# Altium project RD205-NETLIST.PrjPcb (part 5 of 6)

## Sheet 8.SchDoc
size 398 x 287 mm
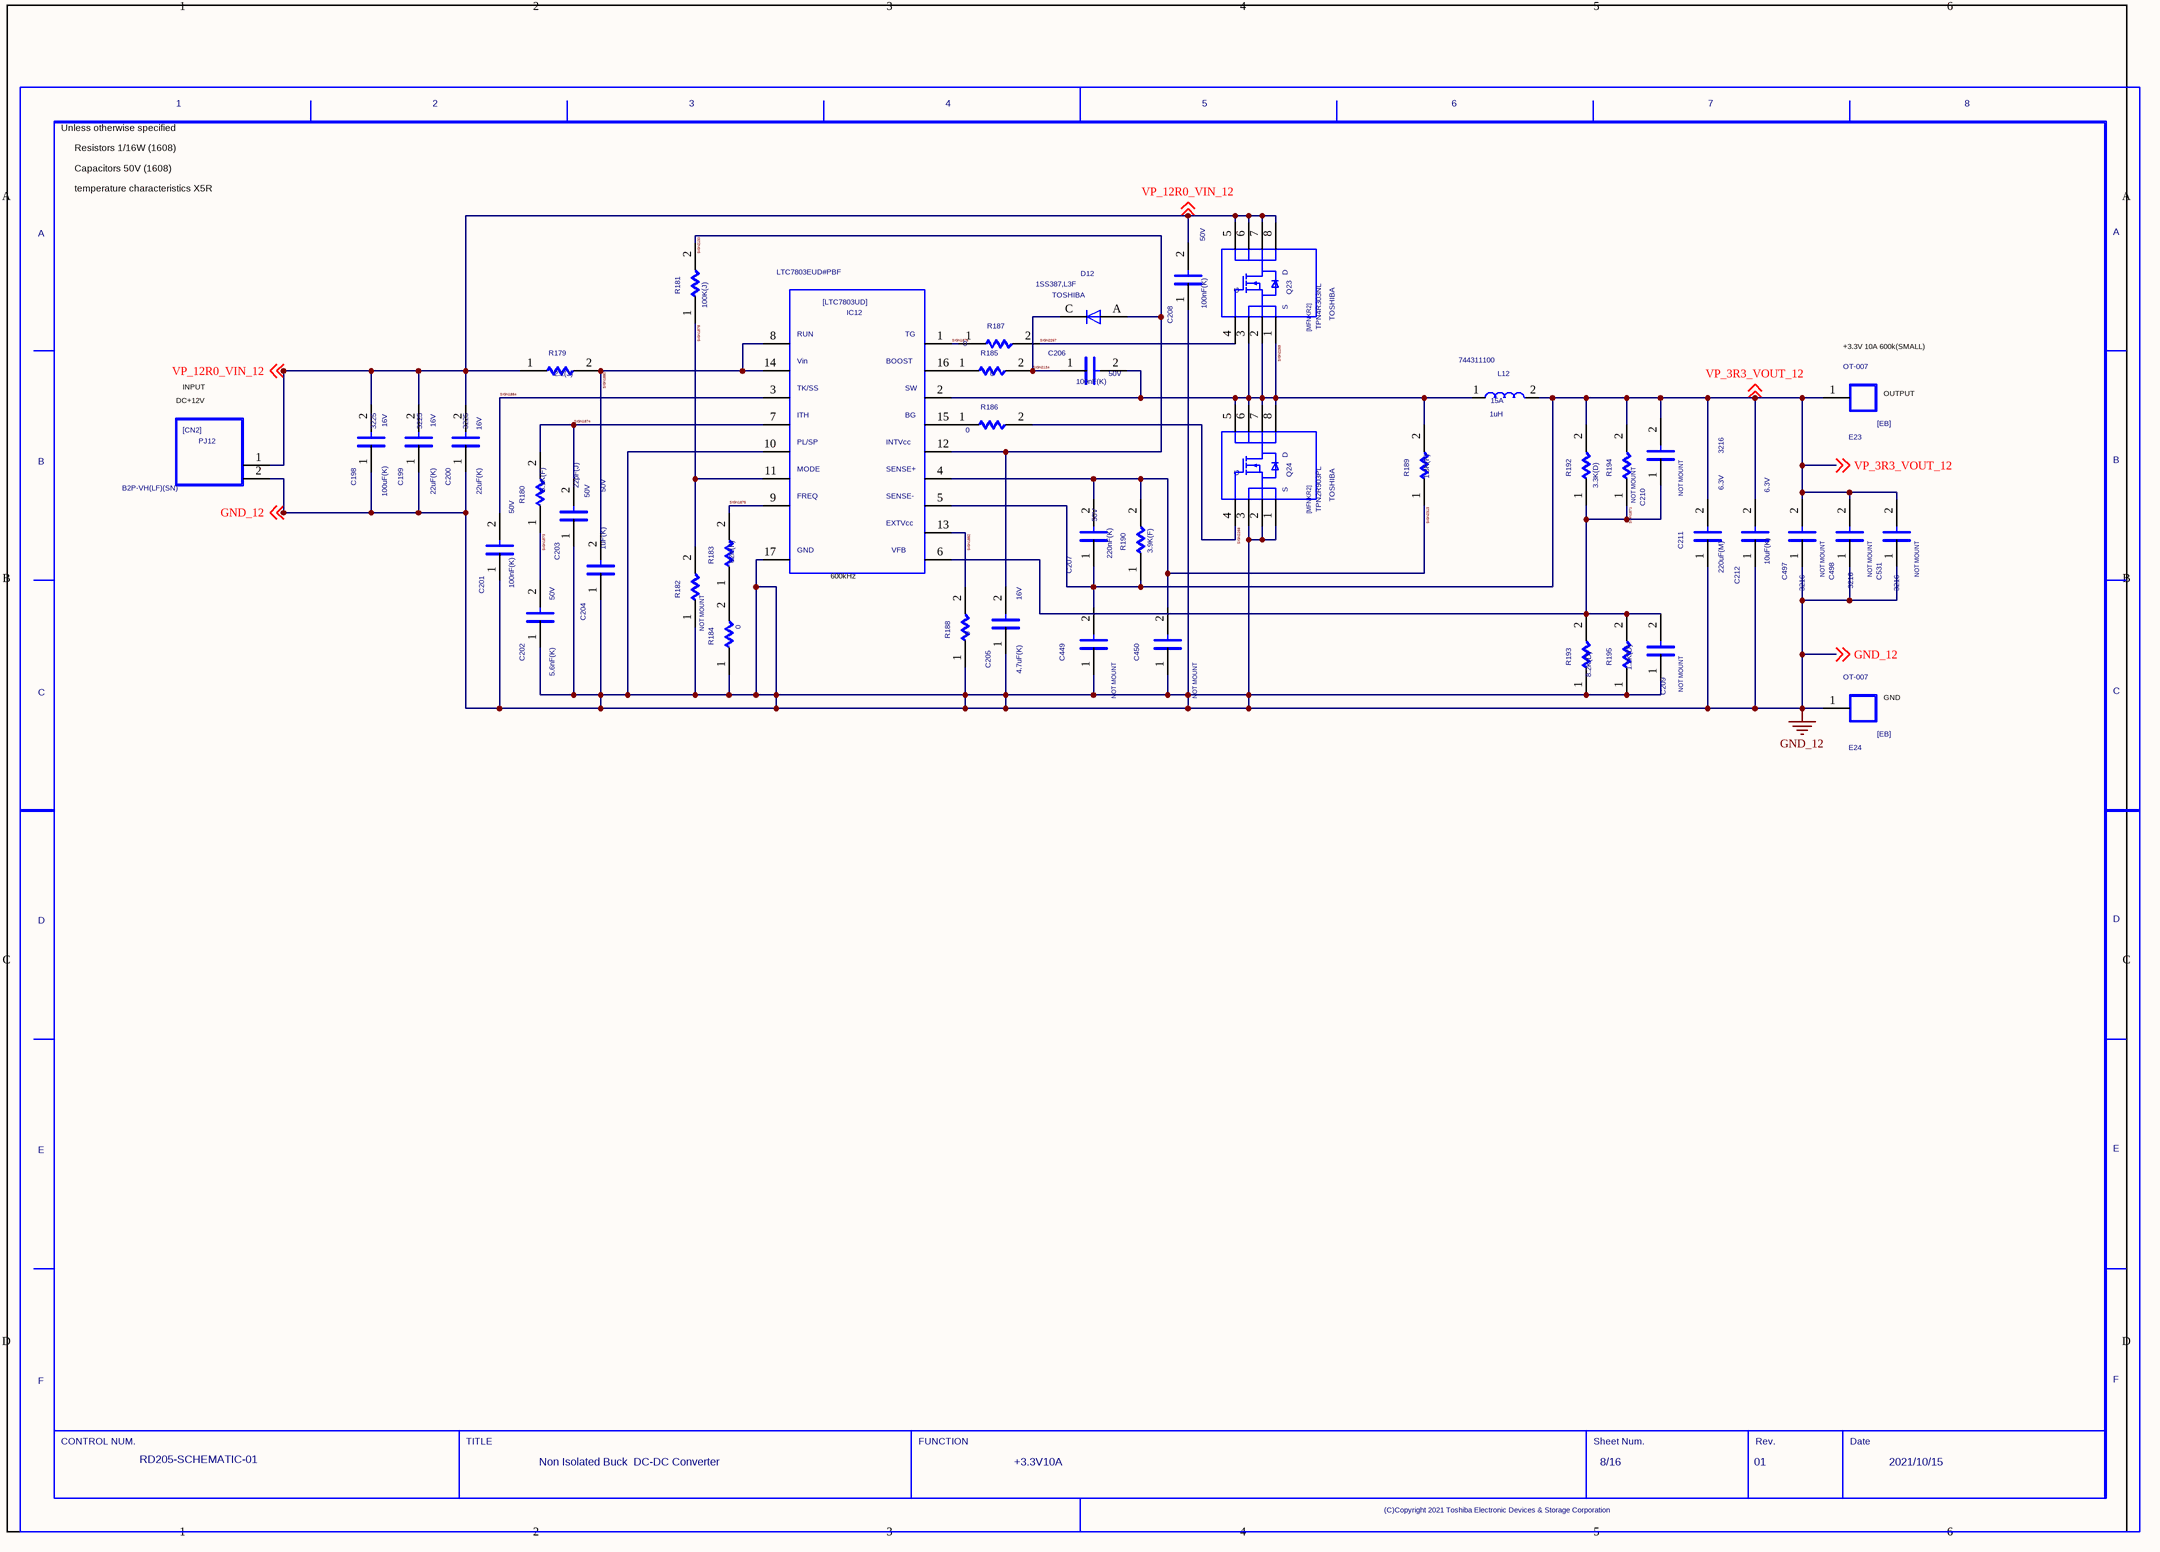
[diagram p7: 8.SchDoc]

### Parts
(Parts that share a designator on the sheet are numbered #1, #2 ... from top to bottom, then left to right.)
C198  SIZECODESMD: 3225  VAL2: 16V  VAL1: 100uF(K)  (hidden comment: C)
C199  SIZECODESMD: 3225  VAL2: 16V  VAL1: 22uF(K)  (hidden comment: C)
C200  SIZECODESMD: 3225  VAL2: 16V  VAL1: 22uF(K)  (hidden comment: C)
C201  VAL2: 50V  VAL1: 100nF(K)  (hidden comment: C)
C202  VAL2: 50V  VAL1: 5.6nF(K)  (hidden comment: C)
C203  VAL2: 50V  VAL1: 22pF(J)  (hidden comment: C)
C204  VAL2: 50V  VAL1: 1uF(K)  (hidden comment: C)
C205  VAL2: 16V  VAL1: 4.7uF(K)  (hidden comment: C)
C206  VAL2: 50V  VAL1: 100nF(K)  (hidden comment: C)
C207  VAL2: 50V  VAL1: 220nF(K)  (hidden comment: C)
C208  VAL2: 50V  VAL1: 100nF(K)  (hidden comment: C)
C209  NOTMOUNT: NOT MOUNT  (hidden comment: C)
C210  NOTMOUNT: NOT MOUNT  (hidden comment: C)
C211  SIZECODESMD: 3216  VAL2: 6.3V  VAL1: 220uF(M)  (hidden comment: C)
C212  VAL2: 6.3V  VAL1: 10uF(K)  (hidden comment: C)
C449  NOTMOUNT: NOT MOUNT  (hidden comment: C)
C450  NOTMOUNT: NOT MOUNT  (hidden comment: C)
C497  NOTMOUNT: NOT MOUNT  SIZECODESMD: 3216  (hidden comment: C)
C498  NOTMOUNT: NOT MOUNT  SIZECODESMD: 3216  (hidden comment: C)
C531  NOTMOUNT: NOT MOUNT  SIZECODESMD: 3216  (hidden comment: C)
D12  USERCOMPTEXT3: TOSHIBA  VAL3: 1SS387,L3F  (hidden comment: D)
E23  VAL3: OT-007  (hidden comment: EB)
E24  VAL3: OT-007  (hidden comment: EB)
IC12  VAL3: LTC7803EUD#PBF  (hidden comment: LTC7803UD)
L12  VAL3: 744311100  VAL2: 15A  VAL1: 1uH  (hidden comment: L)
PJ12  VAL3: B2P-VH(LF)(SN)  (hidden comment: CN2)
Q23  USERCOMPTEXT3: TOSHIBA  VAL3: TPN4R303NL  (hidden comment: MFNKR2)
Q24  USERCOMPTEXT3: TOSHIBA  VAL3: TPN2R903PL  (hidden comment: MFNKR2)
R179  VAL1: 2.2(J)  (hidden comment: R)
R180  VAL1: 5.1K(F)  (hidden comment: R)
R181  VAL1: 100K(J)  (hidden comment: R)
R182  NOTMOUNT: NOT MOUNT  (hidden comment: R)
R183  VAL1: 62K(F)  (hidden comment: R)
R184  VAL1: 0  (hidden comment: R)
R185  VAL1: 0  (hidden comment: R)
R186  VAL1: 0  (hidden comment: R)
R187  VAL1: 0  (hidden comment: R)
R188  VAL1: 0  (hidden comment: R)
R189  VAL1: 1.3K(F)  (hidden comment: R)
R190  VAL1: 3.9K(F)  (hidden comment: R)
R192  VAL1: 3.3K(D)  (hidden comment: R)
R193  VAL1: 8.2K(D)  (hidden comment: R)
R194  NOTMOUNT: NOT MOUNT  (hidden comment: R)
R195  VAL1: 1.2K(D)  (hidden comment: R)
U?#8  DATE: 2021/10/15  SHEETNUMBER: 8/16  TITLE: Non Isolated Buck / DC-DC Converter  REVISION: 01  DRAWINGNUMBER: RD205-SCHEMATIC-01  FUNCTION: +3.3V10A  (hidden comment: WAKU_DEF100)

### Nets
GND_12: C198.1 C199.1 C200.1 C201.1 C202.1 C203.1 C204.1 C205.1 C208.1 C209.1 C211.1 C212.1 C449.1 C450.1 C497.1 C498.1 C531.1 E24.1 IC12.10 IC12.17 PJ12.2 Q24.1 Q24.2 Q24.3 R182.1 R184.1 R188.1 R193.1 R195.1 ; off-sheet GND_12
SIGN1871: C209.2 C210.1 IC12.6 R192.1 R193.2 R194.1 R195.2
SIGN1873: C202.2 R180.1
SIGN1874: C203.2 IC12.7 R180.2
SIGN1875: IC12.9 R183.2
SIGN1876: IC12.1 R187.1
SIGN1878: IC12.11 R181.1 R182.2
SIGN1880: C204.2 IC12.8 IC12.14 R179.2
SIGN1882: IC12.13 R188.2
SIGN1884: C201.2 IC12.3
SIGN2133: C205.2 D12.A IC12.12 R181.2
SIGN2134: C206.1 D12.C R185.2
SIGN2267: Q23.4 R187.2
SIGN2268: Q24.4 R186.2
SIGN2269: C206.2 IC12.2 L12.1 Q23.1 Q23.2 Q23.3 Q24.5 Q24.6 Q24.7 Q24.8 R189.2
SIGN2313: C207.2 C450.2 IC12.4 R189.1 R190.2
VP_3R3_VOUT_12: C207.1 C210.2 C211.2 C212.2 C449.2 C497.2 C498.2 C531.2 E23.1 IC12.5 L12.2 R190.1 R192.2 R194.2 ; off-sheet VP_3R3_VOUT_12
VP_12R0_VIN_12: C198.2 C199.2 C200.2 C208.2 PJ12.1 Q23.5 Q23.6 Q23.7 Q23.8 R179.1 ; off-sheet VP_12R0_VIN_12
NetIC12_15: IC12.15 R186.1
NetIC12_16: IC12.16 R185.1
NetR183_1: R183.1 R184.2

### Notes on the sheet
- Unless otherwise specified
- Capacitors 50V (1608)
- Resistors 1/16W (1608)
- temperature characteristics X5R
- DC+12V
- INPUT
- (near E23) +3.3V 10A 600k(SMALL)
- (near E23) OUTPUT
- (near IC12) 600kHz
- (near E24) GND

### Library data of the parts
C198 = C: SQ_PART_MODEL: CON_100n; FNPARTSNAMEG: CHIP CERAMIC CAPACITOR (3225); USEINPARTSLIST: YES; OriginalSymbolOrigin: (2540,7620); MFSOLDERINGPROP: .; TEMPCHARACTERI2: B; MFFORMINGDIVP: KC; OUMECLASSIFICATION: セラミックコンデンサ; MFMOUNTSYMBOLP: 90; CDMASTERCADCELG: DC903A; PCODE: P03276001115; FNCLASSCODEG: P03-03; MAXGCOUNT: 1; RATEDVOLTAGE: 250; COMPONENTNAME: G36030160049; OUMEMAKER: KYC 京セラ; MFPACKAGEMETHOP: S; NOMINALCAPACITA: 100n; OUMEMAKERKATAMEI: CF32W5R104K250AT; CAPACITANCETOLE: K
C199 C200 = C: SQ_PART_MODEL: CON_22u; FNPARTSNAMEG: CHIP CERAMIC CAPACITOR (3225); USEINPARTSLIST: YES; OriginalSymbolOrigin: (2540,7620); MFSOLDERINGPROP: .; TEMPCHARACTERI2: B; MFFORMINGDIVP: KC; OUMECLASSIFICATION: セラミックコンデンサ; MFMOUNTSYMBOLP: 80; CDMASTERCADCELG: DC903A; PCODE: P03043035626; FNCLASSCODEG: P03-03; MAXGCOUNT: 1; RATEDVOLTAGE: 6.3; COMPONENTNAME: G36030119054; OUMEMAKER: TYD 太陽誘電; MFPACKAGEMETHOP: S; NOMINALCAPACITA: 22u; OUMEMAKERKATAMEI: JMK325BJ226KM-T; CAPACITANCETOLE: K
C201 C206 C208 = C: SQ_PART_MODEL: CON_100n; FNPARTSNAMEG: CHIP CERAMIC CAPACITOR (1608); USEINPARTSLIST: YES; OriginalSymbolOrigin: (2540,7620); MFSOLDERINGPROP: .; TEMPCHARACTERI2: B; MFFORMINGDIVP: KC; OUMECLASSIFICATION: セラミックコンデンサ; SIZECODESMD: 1608; MFMOUNTSYMBOLP: 80; CDMASTERCADCELG: C8100E; PCODE: P03B000000E4; FNCLASSCODEG: P03-03; MAXGCOUNT: 1; RATEDVOLTAGE: 16; COMPONENTNAME: GDM030000598; OUMEMAKER: MRT 村田製作所; MFPACKAGEMETHOP: S; NOMINALCAPACITA: 100n; OUMEMAKERKATAMEI: GRM188B11C104KA01C; CAPACITANCETOLE: K
C202 = C: SQ_PART_MODEL: CON_5.6n; FNPARTSNAMEG: CHIP CERAMIC CAPACITOR (1608); USEINPARTSLIST: YES; OriginalSymbolOrigin: (2540,7620); TOLERANCE: K; ASIMVALUE: 5.6N; MFSOLDERINGPROP: .; TEMPCHARACTERI2: B; MFFORMINGDIVP: KC; OUMECLASSIFICATION: セラミックコンデンサ; SIZECODESMD: 1608; MFMOUNTSYMBOLP: 80; CDMASTERCADCELG: C8100E; PCODE: P03039100222; FNCLASSCODEG: P03-03; MAXGCOUNT: 1; RATEDVOLTAGE: 50; COMPONENTNAME: G36030011068; OUMEMAKER: MRT 村田製作所; MFPACKAGEMETHOP: S; OUMEMAKERKATAMEI: GRM39B562K50PT
C203 = C: SQ_PART_MODEL: CON_22p; FNPARTSNAMEG: CHIP CERAMIC CAPACITOR (1608); USEINPARTSLIST: YES; OriginalSymbolOrigin: (2540,7620); TOLERANCE: J; ASIMVALUE: 22P; CDMASTERCADCELG: C8100E; MFSOLDERINGPROP: .; TEMPCHARACTERI2: CH; MFFORMINGDIVP: KC; OUMECLASSIFICATION: セラミックコンデンサ; SIZECODESMD: 1608; MFMOUNTSYMBOLP: 80; PCODE: P03039A02625; FNCLASSCODEG: P03-03; MAXGCOUNT: 1; RATEDVOLTAGE: 50; COMPONENTNAME: G36030011129; OUMEMAKER: TYD 太陽誘電; MFPACKAGEMETHOP: S; OUMEMAKERKATAMEI: UMK107CH220JZ-T
C204 = C: SQ_PART_MODEL: CON_1u; FNPARTSNAMEG: CHIP CERAMIC CAPACITOR (1608); USEINPARTSLIST: YES; OriginalSymbolOrigin: (2540,7620); MFSOLDERINGPROP: .; TEMPCHARACTERI2: B; MFFORMINGDIVP: KC; OUMECLASSIFICATION: セラミックコンデンサ; SIZECODESMD: 1608; MFMOUNTSYMBOLP: 80; CDMASTERCADCELG: C8100E; PCODE: P03039ACE122; FNCLASSCODEG: P03-03; MAXGCOUNT: 1; RATEDVOLTAGE: 6.3; COMPONENTNAME: G36030104159; OUMEMAKER: KYC 京セラ; MFPACKAGEMETHOP: S; NOMINALCAPACITA: 1u; OUMEMAKERKATAMEI: CM105B105K06ATN; CAPACITANCETOLE: K
C205 = C: SQ_PART_MODEL: CON_4.7u; FNPARTSNAMEG: CHIP CERAMIC CAPACITOR (1608); USEINPARTSLIST: YES; OriginalSymbolOrigin: (2540,7620); MFSOLDERINGPROP: .; TEMPCHARACTERI2: B; MFFORMINGDIVP: KC; OUMECLASSIFICATION: セラミックコンデンサ; SIZECODESMD: 1608; MFMOUNTSYMBOLP: 80; CDMASTERCADCELG: C8100E; PCODE: P03B000000MS; FNCLASSCODEG: P03-03; MAXGCOUNT: 1; RATEDVOLTAGE: 4; COMPONENTNAME: GDM030000053; OUMEMAKER: KYC 京セラ; MFPACKAGEMETHOP: S; NOMINALCAPACITA: 4.7u; OUMEMAKERKATAMEI: CM105B475M04AT; CAPACITANCETOLE: M
C207 = C: SQ_PART_MODEL: CON_220n; FNPARTSNAMEG: CHIP CERAMIC CAPACITOR (1608); PARTCOMMENT: 代表セル<KC0008> がフットプリントに登録されていません。; USEINPARTSLIST: YES; OriginalSymbolOrigin: (2540,7620); MFSOLDERINGPROP: .; TEMPCHARACTERI2: B; MFFORMINGDIVP: KC; OUMECLASSIFICATION: セラミックコンデンサ; SIZECODESMD: 1608; MFMOUNTSYMBOLP: 80; CDMASTERCADCELG: KC0008; PCODE: P03B000001L3; FNCLASSCODEG: P03-03; MAXGCOUNT: 1; RATEDVOLTAGE: 16; COMPONENTNAME: GDM030001129; OUMEMAKER: MRT 村田製作所; MFPACKAGEMETHOP: S; NOMINALCAPACITA: 220n; OUMEMAKERKATAMEI: GRM188B11C224KA01D; CAPACITANCETOLE: K
C209 C210 = C: SQ_PART_MODEL: CON_100p; FNPARTSNAMEG: CHIP CERAMIC CAPACITOR (1608); USEINPARTSLIST: YES; OriginalSymbolOrigin: (2540,7620); TOLERANCE: J; ASIMVALUE: 100P; MFSOLDERINGPROP: .; TEMPCHARACTERI2: CH; MFFORMINGDIVP: KC; OUMECLASSIFICATION: セラミックコンデンサ; SIZECODESMD: 1608; MFMOUNTSYMBOLP: 80; CDMASTERCADCELG: C8100E; PCODE: P03039177125; FNCLASSCODEG: P03-03; MAXGCOUNT: 1; RATEDVOLTAGE: 50; COMPONENTNAME: G36030011365; OUMEMAKER: KYC 京セラ; MFPACKAGEMETHOP: S; OUMEMAKERKATAMEI: CM105CH101J50AT; VAL2: 50V; VAL1: 100pF(J)
C211 = C: SQ_PART_MODEL: CON_22u; FNPARTSNAMEG: CHIP CERAMIC CAPACITOR (3216); USEINPARTSLIST: YES; OriginalSymbolOrigin: (2540,7620); MFSOLDERINGPROP: .; TEMPCHARACTERI2: B; MFFORMINGDIVP: KC; OUMECLASSIFICATION: セラミックコンデンサ; MFMOUNTSYMBOLP: 80; CDMASTERCADCELG: DC901A; PCODE: P03B0000004V; FNCLASSCODEG: P03-03; MAXGCOUNT: 1; RATEDVOLTAGE: 6.3; COMPONENTNAME: GDM030000020; OUMEMAKER: KYC 京セラ; MFPACKAGEMETHOP: S; NOMINALCAPACITA: 22u; OUMEMAKERKATAMEI: CM316B226M06AT; CAPACITANCETOLE: M
C212 = C: SQ_PART_MODEL: CON_1u; FNPARTSNAMEG: CHIP CERAMIC CAPACITOR (1608); PARTCOMMENT: 代表セル<KC0008> がフットプリントに登録されていません。; USEINPARTSLIST: YES; OriginalSymbolOrigin: (2540,7620); MFSOLDERINGPROP: .; TEMPCHARACTERI2: B; MFPACKAGEMETHOP: S; MFFORMINGDIVP: KC; MFMOUNTSYMBOLP: 80; PCODE: P03B000000ZQ; OUMECLASSIFICATION: セラミックコンデンサ; SIZECODESMD: 1608; CDMASTERCADCELG: KC0008; FNCLASSCODEG: P03-03; MAXGCOUNT: 1; RATEDVOLTAGE: 6.3; COMPONENTNAME: GDM030000202; OUMEMAKER: MRT 村田製作所; NOMINALCAPACITA: 1u; OUMEMAKERKATAMEI: GRM185B10J105KE21D; CAPACITANCETOLE: K
C449 C450 = C: SQ_PART_MODEL: CON_220n; FNPARTSNAMEG: CHIP CERAMIC CAPACITOR (1608); PARTCOMMENT: 代表セル<KC0008> がフットプリントに登録されていません。; USEINPARTSLIST: YES; OriginalSymbolOrigin: (2540,7620); MFSOLDERINGPROP: .; TEMPCHARACTERI2: B; MFFORMINGDIVP: KC; OUMECLASSIFICATION: セラミックコンデンサ; SIZECODESMD: 1608; MFMOUNTSYMBOLP: 80; CDMASTERCADCELG: KC0008; PCODE: P03B000001L3; FNCLASSCODEG: P03-03; MAXGCOUNT: 1; RATEDVOLTAGE: 16; COMPONENTNAME: GDM030001129; OUMEMAKER: MRT 村田製作所; MFPACKAGEMETHOP: S; NOMINALCAPACITA: 220n; OUMEMAKERKATAMEI: GRM188B11C224KA01D; VAL2: 16V; VAL1: 220nF(K); CAPACITANCETOLE: K
C497 C498 C531 = C: SQ_PART_MODEL: CON_22u; FNPARTSNAMEG: CHIP CERAMIC CAPACITOR (3216); USEINPARTSLIST: YES; OriginalSymbolOrigin: (2540,7620); MFSOLDERINGPROP: .; TEMPCHARACTERI2: B; MFFORMINGDIVP: KC; OUMECLASSIFICATION: セラミックコンデンサ; MFMOUNTSYMBOLP: 80; CDMASTERCADCELG: DC901A; PCODE: P03B0000004V; FNCLASSCODEG: P03-03; MAXGCOUNT: 1; RATEDVOLTAGE: 6.3; COMPONENTNAME: GDM030000020; OUMEMAKER: KYC 京セラ; MFPACKAGEMETHOP: S; NOMINALCAPACITA: 22u; OUMEMAKERKATAMEI: CM316B226M06AT; VAL2: 6.3V; VAL1: 22uF(M); CAPACITANCETOLE: M
D12 = D: FNPARTSNAMEG: DIODE; USEINPARTSLIST: YES; PARTNAME: GDM420000143; SAVEAREA0: -565,-171,12979,8058; SAVECOUNT: 1; TIME: 14:49:55; UPDATEUSER: 19870035; UPDATETIME: 14:20:16; OriginalSymbolOrigin: (5080,5080); FORWARDVOLTAGEM: 0; MAXREVERSEVOLTA: 80; COMPONENTNAME: GDM420000143_package; MFSOLDERINGPROP: .; OUMEMAKER: TSB 東芝（ＹＰＳＳ）; QUADMODEL: dummymodel; MFPACKAGEMETHOP: S; MFFORMINGDIVP: MM; MOUNTINGFORMSMD: SMD; OUMECLASSIFICATION: 小信号ダイオード; OUMEMAKERKATAMEI: 1SS387(TPH3,F); CDMASTERCADCELG: D8101D; PCODE: P42B0000008E; FNCLASSCODEG: P42-01
E23 E24 = EB: FNPARTSNAMEG: TERMINAL; USEINPARTSLIST: YES; PARTNAME: 5P9L1232P001; OUMEPARTTYPE: TB; OriginalSymbolOrigin: (2540,12700); COMPONENTNAME: 5P9L1232P001_package; MAXGCOUNT: 1; MFSOLDERINGPROP: .; OUMEMAKER: オサダ; QUADMODEL: dummymodel; MFPACKAGEMETHOP: I; MFFORMINGDIVP: OD; OUMECLASSIFICATION: 端子台、端子板; CDMASTERCADCELG: DE0009; KIND: PBS; PCODE: P29045001117; TERMINALSTYLE: SC; FNCLASSCODEG: P29-01
IC12 = LTC7803UD: USEINPARTSLIST: YES; SAVECOUNT: 29; SAVEAREA0: -53177,0,89020,58420; TIME: 16:14:14; UPDATEUSER: q91866sr; UPDATETIME: 13:15:36; OriginalSymbolOrigin: (5080,55880); MAXGCOUNT: 1; COMPONENTNAME: LTC7803UD_LTC7803UD; OUMEMAKER: ANALOG DEVICES
L12 = L: USEINPARTSLIST: YES; OriginalSymbolOrigin: (2540,5080); MAXGCOUNT: 1; COMPONENTNAME: L_L; OUMEMAKER: WURTH
PJ12 = CN2: FNPARTSNAMEG: 3.96PITCH NYLON CONNECTOR; USEINPARTSLIST: YES; PARTNAME: G36220114012; OUMEPARTTYPE: CN; OriginalSymbolOrigin: (2540,15240); MAXGCOUNT: 1; RATEDCURRENT: 7; COMPONENTNAME: G36220114012_package; MFSOLDERINGPROP: .; OUMEMAKER: JST 日本圧着端子製造; NUMBEROFCONTACT: 2; QUADMODEL: dummymodel; MFPACKAGEMETHOP: I; MFFORMINGDIVP: CU; CONTACTPITCH: 3.96m; OUMEMAKERKATAMEI: B2P-VH; CDMASTERCADCELG: DPJ514; PCODE: P22346001114; TERMINALSTYLE: PW; FNCLASSCODEG: P22-10
Q23 Q24 = MFNKR2: USEINPARTSLIST: YES; PARTNAME: TPN1R603PL; SAVEAREA0: -9199,-39,32138,22820; TIME: 18:57:44; UPDATEUSER: q91866sr; UPDATETIME: 12:36:02; SAVECOUNT: 10; OriginalSymbolOrigin: (5080,20320); MAXGCOUNT: 1; COMPONENTNAME: MFNKR2_MFNKR2
R179 = R: SQ_PART_MODEL: RES_2.2; FNPARTSNAMEG: CHIP RESISTOR (1608); USEINPARTSLIST: YES; OriginalSymbolOrigin: (5080,5080); TOLERANCE: J; ASIMVALUE: 2.2; MAXGCOUNT: 1; COMPONENTNAME: G36010011507; MFSOLDERINGPROP: .; OUMEMAKER: NAE 松下電子部品; MFPACKAGEMETHOP: S; MFFORMINGDIVP: KC; MOUNTINGFORMSMD: SMD; OUMECLASSIFICATION: 表面実装用固定抵抗器; MFMOUNTSYMBOLP: 80; POWERRATING: 63m; OUMEMAKERKATAMEI: ERJ3GEYJ2R2V; NUMBEROFELEMENT: 0; VAL2: 62.5mW; CDMASTERCADCELG: DR802R; PCODE: P01042157622; FNCLASSCODEG: P01-08
R180 = R: SQ_PART_MODEL: RES_5.1K; FNPARTSNAMEG: CHIP RESISTOR (1608); USEINPARTSLIST: YES; OriginalSymbolOrigin: (5080,5080); MAXGCOUNT: 1; COMPONENTNAME: G5101105N106; MFSOLDERINGPROP: .; OUMEMAKER: NAE 松下電子部品; MFPACKAGEMETHOP: S; MFFORMINGDIVP: KC; MOUNTINGFORMSMD: SMD; OUMECLASSIFICATION: 表面実装用固定抵抗器; RESISTANCETOLER: F; MFMOUNTSYMBOLP: 80; POWERRATING: 63m; OUMEMAKERKATAMEI: ERJ3GEYF512V; NOMINALRESISTAN: 5.1K; NUMBEROFELEMENT: 0; VAL2: 62.5mW; CDMASTERCADCELG: DR802R; PCODE: P01042378621; FNCLASSCODEG: P01-08
R181 = R: SQ_PART_MODEL: RES_100K; FNPARTSNAMEG: CHIP RESISTOR (1608); USEINPARTSLIST: YES; OriginalSymbolOrigin: (5080,5080); TOLERANCE: J; ASIMVALUE: 100K; MFSOLDERINGPROP: .; MFPACKAGEMETHOP: S; MFFORMINGDIVP: KC; MOUNTINGFORMSMD: SMD; MFMOUNTSYMBOLP: 80; NUMBEROFELEMENT: 0; PCODE: P01042047220; MAXGCOUNT: 1; COMPONENTNAME: G36010011057; OUMEMAKER: HDK 北陸電気工業; OUMECLASSIFICATION: 表面実装用固定抵抗器; POWERRATING: 63m; OUMEMAKERKATAMEI: CR1/16 104JV; VAL2: 62.5mW; CDMASTERCADCELG: DR802R; FNCLASSCODEG: P01-08
R182 = R: SQ_PART_MODEL: RES_10; FNPARTSNAMEG: CHIP RESISTOR (1608); USEINPARTSLIST: YES; OriginalSymbolOrigin: (5080,5080); TOLERANCE: F; ASIMVALUE: 10; MFSOLDERINGPROP: .; MFPACKAGEMETHOP: S; MFFORMINGDIVP: KC; MOUNTINGFORMSMD: SMD; MFMOUNTSYMBOLP: 80; NUMBEROFELEMENT: 0; PCODE: P01042036620; MAXGCOUNT: 1; COMPONENTNAME: G36010104063; OUMEMAKER: NAE 松下電子部品; OUMECLASSIFICATION: 表面実装用固定抵抗器; POWERRATING: 63m; OUMEMAKERKATAMEI: ERJ3GEYF100V; VAL2: 62.5mW; VAL1: 10(F); CDMASTERCADCELG: DR802R; FNCLASSCODEG: P01-08
R183 = R: SQ_PART_MODEL: RES_62K; FNPARTSNAMEG: CHIP RESISTOR (1608); USEINPARTSLIST: YES; OriginalSymbolOrigin: (5080,5080); MAXGCOUNT: 1; COMPONENTNAME: GDM010001037; MFSOLDERINGPROP: .; OUMEMAKER: NAE 松下電子部品; MFPACKAGEMETHOP: S; MFFORMINGDIVP: KC; MOUNTINGFORMSMD: SMD; OUMECLASSIFICATION: 表面実装用固定抵抗器; RESISTANCETOLER: F; MFMOUNTSYMBOLP: 80; POWERRATING: 63m; OUMEMAKERKATAMEI: ERJ3GEYF623V; NOMINALRESISTAN: 62K; NUMBEROFELEMENT: 0; VAL2: 62.5mW; CDMASTERCADCELG: DR802R; PCODE: P01042441622; FNCLASSCODEG: P01-08
R184 = R: SQ_PART_MODEL: RES_160K; FNPARTSNAMEG: CHIP RESISTOR (1608); USEINPARTSLIST: YES; OriginalSymbolOrigin: (5080,5080); MAXGCOUNT: 1; COMPONENTNAME: G51011061108; MFSOLDERINGPROP: .; OUMEMAKER: HDK 北陸電気工業; MFPACKAGEMETHOP: S; MFFORMINGDIVP: KC; MOUNTINGFORMSMD: SMD; OUMECLASSIFICATION: 表面実装用固定抵抗器; RESISTANCETOLER: F; MFMOUNTSYMBOLP: 80; POWERRATING: 63m; OUMEMAKERKATAMEI: CR1/16 164FV; NOMINALRESISTAN: 160K; VAL2: 62.5mW; CDMASTERCADCELG: DR802R; PCODE: P01042125225; FNCLASSCODEG: P01-08
R185 R188 = R: SQ_PART_MODEL: RES_10; FNPARTSNAMEG: CHIP RESISTOR (1608); USEINPARTSLIST: YES; OriginalSymbolOrigin: (5080,5080); TOLERANCE: F; ASIMVALUE: 10; MFSOLDERINGPROP: .; MFPACKAGEMETHOP: S; MFFORMINGDIVP: KC; MOUNTINGFORMSMD: SMD; MFMOUNTSYMBOLP: 80; PCODE: P01042036620; MAXGCOUNT: 1; COMPONENTNAME: G36010104063; OUMEMAKER: NAE 松下電子部品; OUMECLASSIFICATION: 表面実装用固定抵抗器; POWERRATING: 63m; OUMEMAKERKATAMEI: ERJ3GEYF100V; VAL2: 62.5mW; CDMASTERCADCELG: DR802R; FNCLASSCODEG: P01-08
R186 R187 = R: SQ_PART_MODEL: RES_10; FNPARTSNAMEG: CHIP RESISTOR (2012); USEINPARTSLIST: YES; OriginalSymbolOrigin: (5080,5080); MAXGCOUNT: 1; TOLERANCE: F; COMPONENTNAME: 5P9L1083P100; MFSOLDERINGPROP: .; OUMEMAKER: 北陸電気工業; MFPACKAGEMETHOP: S; MFFORMINGDIVP: KC; MOUNTINGFORMSMD: SMD; OUMECLASSIFICATION: 表面実装用固定抵抗器; ASIMVALUE: 10; MFMOUNTSYMBOLP: 90; POWERRATING: 100m; OUMEMAKERKATAMEI: CR1/10 100FV Pb(F); VAL2: 125mW; CDMASTERCADCELG: DR910A; PCODE: P01043091222; FNCLASSCODEG: P01-08
R189 = R: SQ_PART_MODEL: RES_1.3K; FNPARTSNAMEG: CHIP RESISTOR (1608); USEINPARTSLIST: YES; OriginalSymbolOrigin: (5080,5080); TOLERANCE: F; ASIMVALUE: 1.3K; MAXGCOUNT: 1; COMPONENTNAME: G36010104049; MFSOLDERINGPROP: .; OUMEMAKER: HDK 北陸電気工業; MFPACKAGEMETHOP: S; MFFORMINGDIVP: KC; MOUNTINGFORMSMD: SMD; OUMECLASSIFICATION: 表面実装用固定抵抗器; MFMOUNTSYMBOLP: 80; POWERRATING: 63m; OUMEMAKERKATAMEI: CR1/16 132FV; NUMBEROFELEMENT: 0; VAL2: 62.5mW; CDMASTERCADCELG: DR802R; PCODE: P01042017223; FNCLASSCODEG: P01-08
R190 = R: SQ_PART_MODEL: RES_3.9K; FNPARTSNAMEG: CHIP RESISTOR (1608); USEINPARTSLIST: YES; OriginalSymbolOrigin: (5080,5080); MAXGCOUNT: 1; COMPONENTNAME: G36010104254; OUMEMAKER: HDK 北陸電気工業; MOUNTINGFORMSMD: SMD; OUMECLASSIFICATION: 表面実装用固定抵抗器; RESISTANCETOLER: F; POWERRATING: 63m; OUMEMAKERKATAMEI: CR1/16 392FV; NOMINALRESISTAN: 3.9K; CDMASTERCADCELG: DR802R; MFSOLDERINGPROP: .; MFPACKAGEMETHOP: S; MFFORMINGDIVP: KC; MFMOUNTSYMBOLP: 80; NUMBEROFELEMENT: 0; VAL2: 62.5mW; PCODE: P01042262227; FNCLASSCODEG: P01-08
R192 = R: SQ_PART_MODEL: RES_3.3K; FNPARTSNAMEG: CHIP RESISTOR (1608); USEINPARTSLIST: YES; OriginalSymbolOrigin: (5080,5080); MAXGCOUNT: 1; COMPONENTNAME: G36010014485; MFSOLDERINGPROP: .; OUMEMAKER: SSM 進工業; MFPACKAGEMETHOP: S; MFFORMINGDIVP: KC; MOUNTINGFORMSMD: SMD; OUMECLASSIFICATION: 表面実装用固定抵抗器; RESISTANCETOLER: D; MFMOUNTSYMBOLP: 80; POWERRATING: 63m; OUMEMAKERKATAMEI: RR0816P-332-D; NOMINALRESISTAN: 3.3K; NUMBEROFELEMENT: 0; VAL2: 62.5mW; CDMASTERCADCELG: DR802R; PCODE: P01042249822; FNCLASSCODEG: P01-08
R193 = R: ICX_PART_MODEL: RES_8.2K; FNPARTSNAMEG: CHIP RESISTOR (1608); OriginalSymbolOrigin: (5080,5080); FNCLASSCODEG: P01-08; PCODE: P01117051114; CDMASTERCADCELG: DR802R; USEWITHSCHEMA: YES; VAL2: 62.5mW; NUMBEROFELEMENT: 0; NOMINALRESISTAN: 8.2K; OUMEMAKERKATAMEI: RK73G1JTD822D; POWERRATING: 63m; MFMOUNTSYMBOLP: 80; RESISTANCETOLER: D; FUNCTION: G36010129479; OUMECLASSIFICATION: 表面実装用固定抵抗器; MOUNTINGFORMSMD: SMD; MFFORMINGDIVP: KC; MFPACKAGEMETHOP: S; OUMEMAKER: KOA ＫＯＡ; MFSOLDERINGPROP: .; MAXGCOUNT: 1
R194 = R: SQ_PART_MODEL: RES_3.3K; FNPARTSNAMEG: CHIP RESISTOR (1608); USEINPARTSLIST: YES; OriginalSymbolOrigin: (5080,5080); TOLERANCE: F; ASIMVALUE: 3.3K; MAXGCOUNT: 1; COMPONENTNAME: G36010027027; MFSOLDERINGPROP: .; OUMEMAKER: ROH ロー・; MFPACKAGEMETHOP: S; MFFORMINGDIVP: KC; MOUNTINGFORMSMD: SMD; OUMECLASSIFICATION: 表面実装用固定抵抗器; MFMOUNTSYMBOLP: 80; POWERRATING: 63m; OUMEMAKERKATAMEI: MCR03EZPFX3301; NUMBEROFELEMENT: 0; VAL2: 62.5mW; VAL1: 3.3K(F); CDMASTERCADCELG: DR802R; PCODE: P01042250729; FNCLASSCODEG: P01-08
R195 = R: ICX_PART_MODEL: RES_1.2K; FNPARTSNAMEG: CHIP RESISTOR (1608); OriginalSymbolOrigin: (5080,5080); FNCLASSCODEG: P01-08; PCODE: P01117031116; CDMASTERCADCELG: DR802R; USEWITHSCHEMA: YES; VAL2: 62.5mW; NUMBEROFELEMENT: 0; NOMINALRESISTAN: 1.2K; OUMEMAKERKATAMEI: RK73G1JTD122D; POWERRATING: 63m; MFMOUNTSYMBOLP: 80; RESISTANCETOLER: D; FUNCTION: G36010129271; OUMECLASSIFICATION: 表面実装用固定抵抗器; MOUNTINGFORMSMD: SMD; MFFORMINGDIVP: KC; MFPACKAGEMETHOP: S; OUMEMAKER: KOA ＫＯＡ; MFSOLDERINGPROP: .; MAXGCOUNT: 1
U?#8 = WAKU_DEF100: PLOTTIME: HH:MM; SAVEAREA0: 330961,54,387907,31546; TIME: 19:23:07; UPDATEUSER: t5459927; UPDATETIME: 15:33:40; SAVECOUNT: 6; OriginalSymbolOrigin: (10160,284480); DESIGNED: ***

## Sheet 9.SchDoc
size 398 x 287 mm
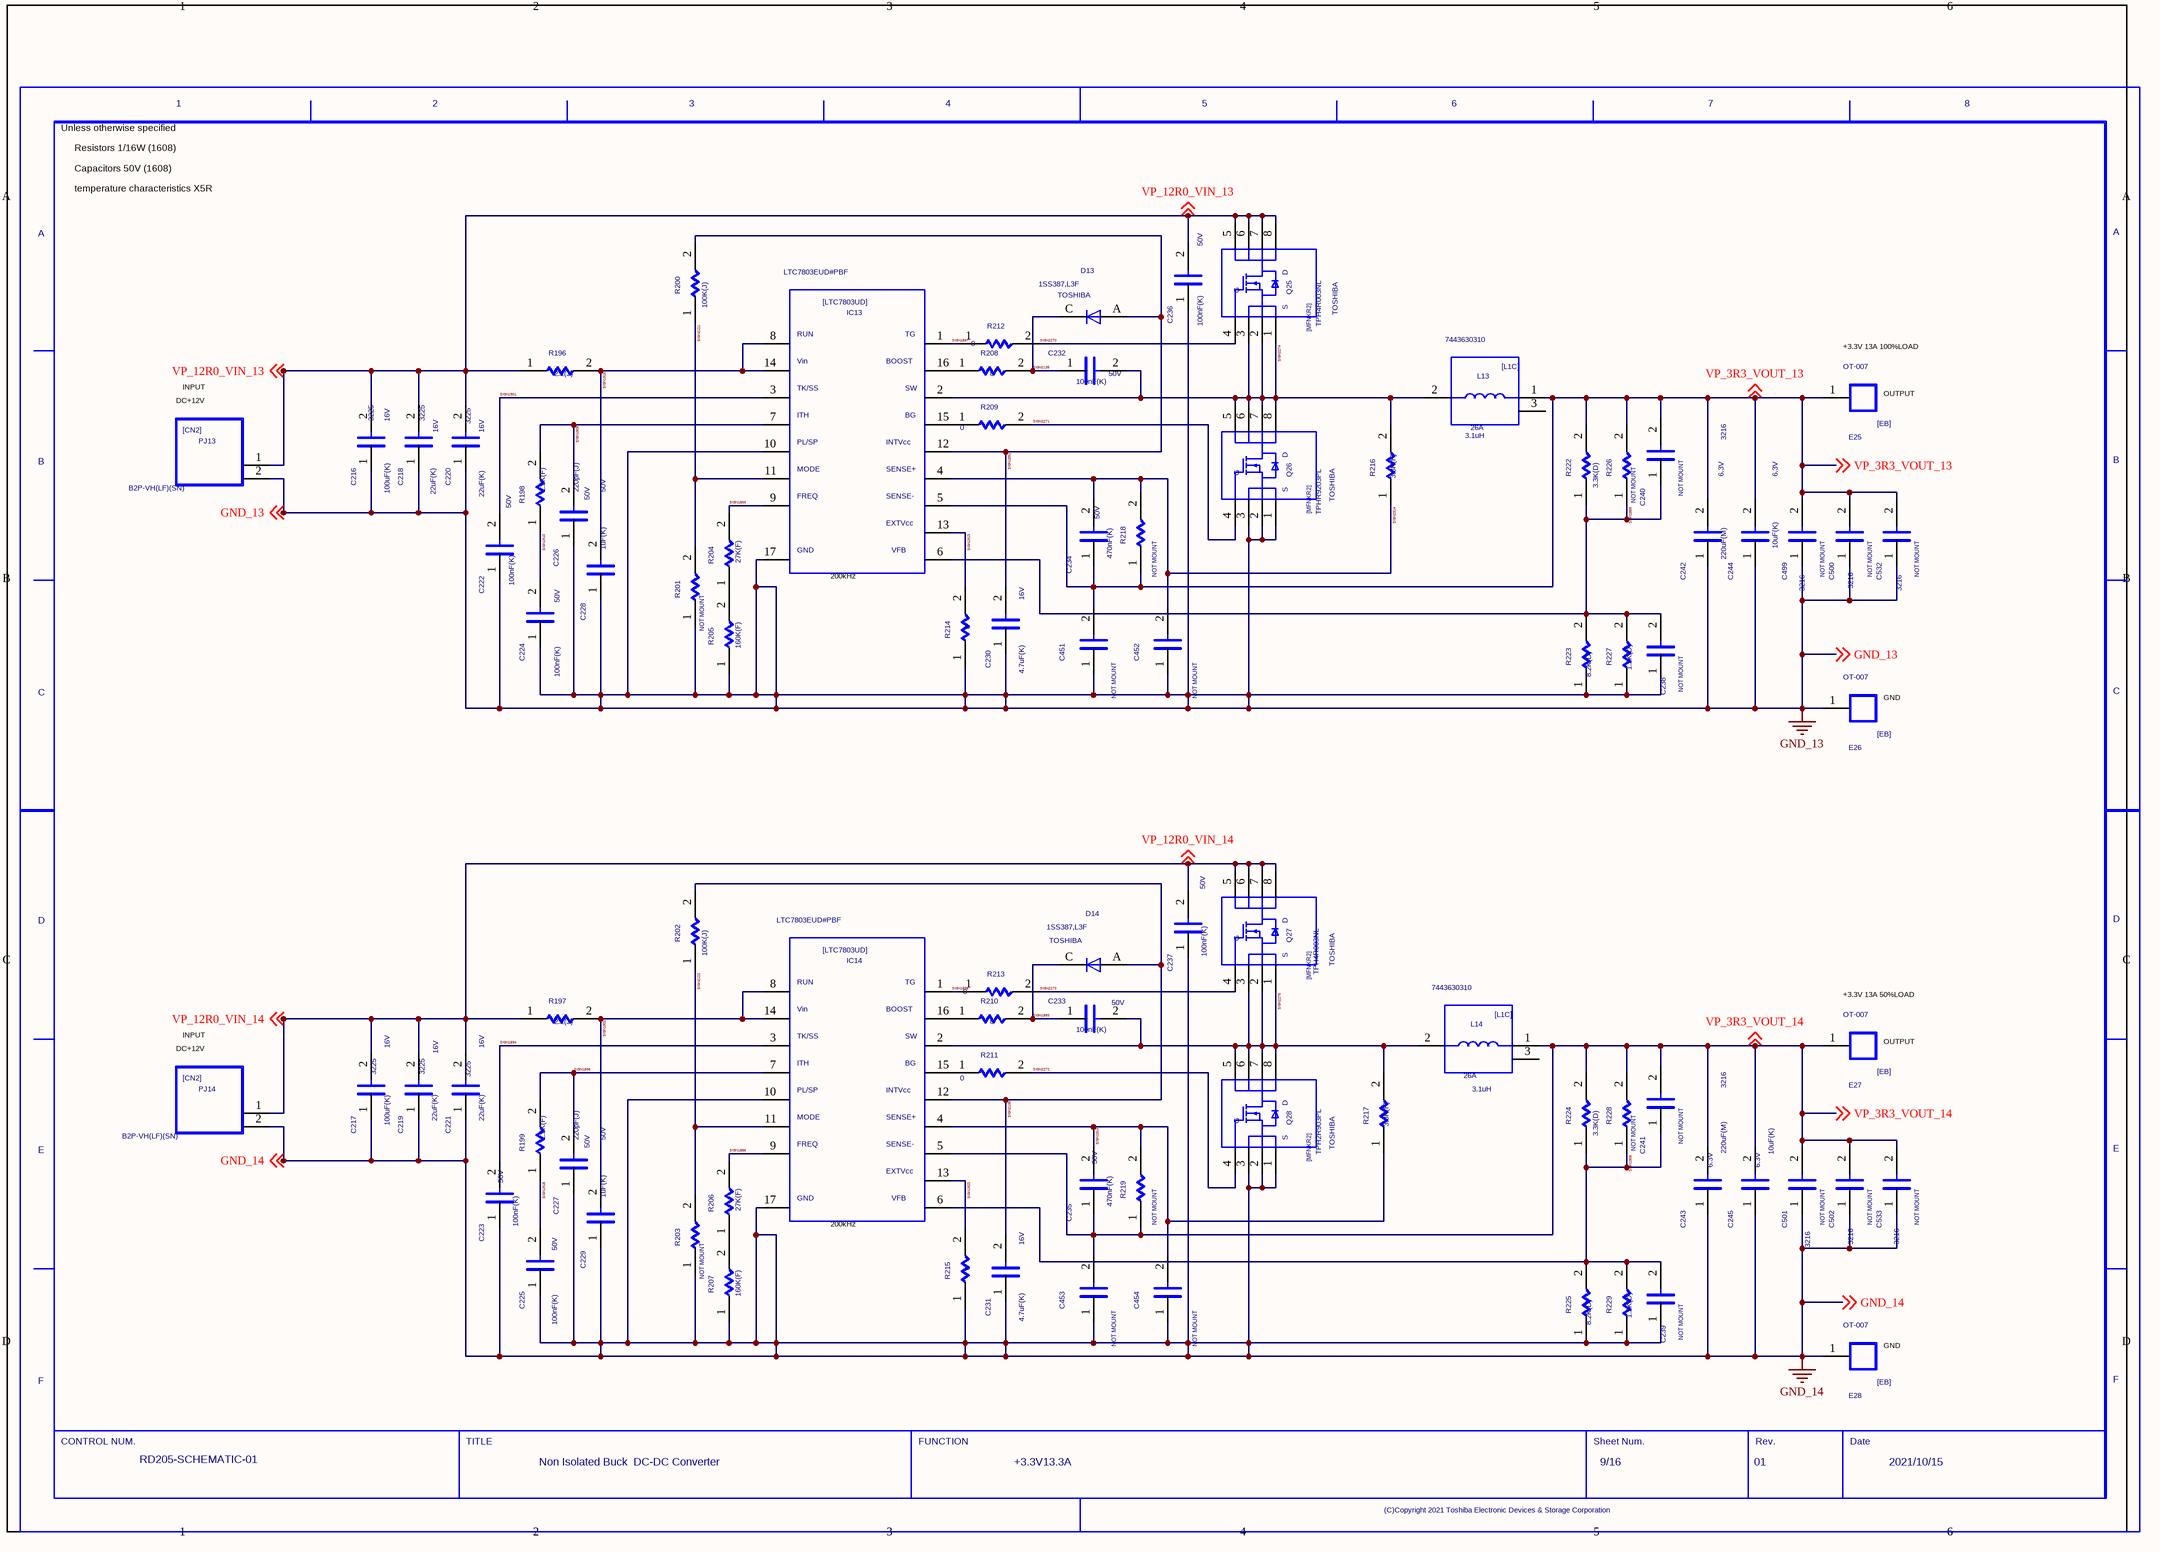
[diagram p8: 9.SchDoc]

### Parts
(Parts that share a designator on the sheet are numbered #1, #2 ... from top to bottom, then left to right.)
C216  SIZECODESMD: 3225  VAL2: 16V  VAL1: 100uF(K)  (hidden comment: C)
C217  SIZECODESMD: 3225  VAL2: 16V  VAL1: 100uF(K)  (hidden comment: C)
C218  SIZECODESMD: 3225  VAL2: 16V  VAL1: 22uF(K)  (hidden comment: C)
C219  SIZECODESMD: 3225  VAL2: 16V  VAL1: 22uF(K)  (hidden comment: C)
C220  SIZECODESMD: 3225  VAL2: 16V  VAL1: 22uF(K)  (hidden comment: C)
C221  SIZECODESMD: 3225  VAL2: 16V  VAL1: 22uF(K)  (hidden comment: C)
C222  VAL2: 50V  VAL1: 100nF(K)  (hidden comment: C)
C223  VAL2: 50V  VAL1: 100nF(K)  (hidden comment: C)
C224  VAL2: 50V  VAL1: 100nF(K)  (hidden comment: C)
C225  VAL2: 50V  VAL1: 100nF(K)  (hidden comment: C)
C226  VAL2: 50V  VAL1: 220pF(J)  (hidden comment: C)
C227  VAL2: 50V  VAL1: 220pF(J)  (hidden comment: C)
C228  VAL2: 50V  VAL1: 1uF(K)  (hidden comment: C)
C229  VAL2: 50V  VAL1: 1uF(K)  (hidden comment: C)
C230  VAL2: 16V  VAL1: 4.7uF(K)  (hidden comment: C)
C231  VAL2: 16V  VAL1: 4.7uF(K)  (hidden comment: C)
C232  VAL2: 50V  VAL1: 100nF(K)  (hidden comment: C)
C233  VAL2: 50V  VAL1: 100nF(K)  (hidden comment: C)
C234  VAL2: 50V  VAL1: 470nF(K)  (hidden comment: C)
C235  VAL2: 50V  VAL1: 470nF(K)  (hidden comment: C)
C236  VAL2: 50V  VAL1: 100nF(K)  (hidden comment: C)
C237  VAL2: 50V  VAL1: 100nF(K)  (hidden comment: C)
C238  NOTMOUNT: NOT MOUNT  (hidden comment: C)
C239  NOTMOUNT: NOT MOUNT  (hidden comment: C)
C240  NOTMOUNT: NOT MOUNT  (hidden comment: C)
C241  NOTMOUNT: NOT MOUNT  (hidden comment: C)
C242  SIZECODESMD: 3216  VAL2: 6.3V  VAL1: 220uF(M)  (hidden comment: C)
C243  SIZECODESMD: 3216  VAL2: 6.3V  VAL1: 220uF(M)  (hidden comment: C)
C244  VAL2: 6.3V  VAL1: 10uF(K)  (hidden comment: C)
C245  VAL2: 6.3V  VAL1: 10uF(K)  (hidden comment: C)
C451  NOTMOUNT: NOT MOUNT  (hidden comment: C)
C452  NOTMOUNT: NOT MOUNT  (hidden comment: C)
C453  NOTMOUNT: NOT MOUNT  (hidden comment: C)
C454  NOTMOUNT: NOT MOUNT  (hidden comment: C)
C499  NOTMOUNT: NOT MOUNT  SIZECODESMD: 3216  (hidden comment: C)
C500  NOTMOUNT: NOT MOUNT  SIZECODESMD: 3216  (hidden comment: C)
C501  NOTMOUNT: NOT MOUNT  SIZECODESMD: 3216  (hidden comment: C)
C502  NOTMOUNT: NOT MOUNT  SIZECODESMD: 3216  (hidden comment: C)
C532  NOTMOUNT: NOT MOUNT  SIZECODESMD: 3216  (hidden comment: C)
C533  NOTMOUNT: NOT MOUNT  SIZECODESMD: 3216  (hidden comment: C)
D13  USERCOMPTEXT3: TOSHIBA  VAL3: 1SS387,L3F  (hidden comment: D)
D14  USERCOMPTEXT3: TOSHIBA  VAL3: 1SS387,L3F  (hidden comment: D)
E25  VAL3: OT-007  (hidden comment: EB)
E26  VAL3: OT-007  (hidden comment: EB)
E27  VAL3: OT-007  (hidden comment: EB)
E28  VAL3: OT-007  (hidden comment: EB)
IC13  VAL3: LTC7803EUD#PBF  (hidden comment: LTC7803UD)
IC14  VAL3: LTC7803EUD#PBF  (hidden comment: LTC7803UD)
L13  VAL3: 7443630310  VAL2: 26A  VAL1: 3.1uH  (hidden comment: L1C)
L14  VAL3: 7443630310  VAL2: 26A  VAL1: 3.1uH  (hidden comment: L1C)
PJ13  VAL3: B2P-VH(LF)(SN)  (hidden comment: CN2)
PJ14  VAL3: B2P-VH(LF)(SN)  (hidden comment: CN2)
Q25  USERCOMPTEXT3: TOSHIBA  VAL3: TPH4R003NL  (hidden comment: MFNKR2)
Q26  USERCOMPTEXT3: TOSHIBA  VAL3: TPHR9203PL  (hidden comment: MFNKR2)
Q27  USERCOMPTEXT3: TOSHIBA  VAL3: TPH4R003NL  (hidden comment: MFNKR2)
Q28  USERCOMPTEXT3: TOSHIBA  VAL3: TPH2R903PL  (hidden comment: MFNKR2)
R196  VAL1: 2.2(J)  (hidden comment: R)
R197  VAL1: 2.2(J)  (hidden comment: R)
R198  VAL1: 1.3K(F)  (hidden comment: R)
R199  VAL1: 1.3K(F)  (hidden comment: R)
R200  VAL1: 100K(J)  (hidden comment: R)
R201  NOTMOUNT: NOT MOUNT  (hidden comment: R)
R202  VAL1: 100K(J)  (hidden comment: R)
R203  NOTMOUNT: NOT MOUNT  (hidden comment: R)
R204  VAL1: 27K(F)  (hidden comment: R)
R205  VAL1: 160K(F)  (hidden comment: R)
R206  VAL1: 27K(F)  (hidden comment: R)
R207  VAL1: 160K(F)  (hidden comment: R)
R208  VAL1: 0  (hidden comment: R)
R209  VAL1: 0  (hidden comment: R)
R210  VAL1: 0  (hidden comment: R)
R211  VAL1: 0  (hidden comment: R)
R212  VAL1: 0  (hidden comment: R)
R213  VAL1: 0  (hidden comment: R)
R214  VAL1: 0  (hidden comment: R)
R215  VAL1: 0  (hidden comment: R)
R216  VAL1: 3.3K(F)  (hidden comment: R)
R217  VAL1: 3.3K(F)  (hidden comment: R)
R218  NOTMOUNT: NOT MOUNT  (hidden comment: R)
R219  NOTMOUNT: NOT MOUNT  (hidden comment: R)
R222  VAL1: 3.3K(D)  (hidden comment: R)
R223  VAL1: 8.2K(D)  (hidden comment: R)
R224  VAL1: 3.3K(D)  (hidden comment: R)
R225  VAL1: 8.2K(D)  (hidden comment: R)
R226  NOTMOUNT: NOT MOUNT  (hidden comment: R)
R227  VAL1: 1.2K(D)  (hidden comment: R)
R228  NOTMOUNT: NOT MOUNT  (hidden comment: R)
R229  VAL1: 1.2K(D)  (hidden comment: R)
U?#9  DATE: 2021/10/15  SHEETNUMBER: 9/16  TITLE: Non Isolated Buck / DC-DC Converter  REVISION: 01  DRAWINGNUMBER: RD205-SCHEMATIC-01  FUNCTION: +3.3V13.3A  (hidden comment: WAKU_DEF100)

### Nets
GND_13: C216.1 C218.1 C220.1 C222.1 C224.1 C226.1 C228.1 C230.1 C236.1 C238.1 C242.1 C244.1 C451.1 C452.1 C499.1 C500.1 C532.1 E26.1 IC13.10 IC13.17 PJ13.2 Q26.1 Q26.2 Q26.3 R201.1 R205.1 R214.1 R223.1 R227.1 ; off-sheet GND_13
GND_14: C217.1 C219.1 C221.1 C223.1 C225.1 C227.1 C229.1 C231.1 C237.1 C239.1 C243.1 C245.1 C453.1 C454.1 C501.1 C502.1 C533.1 E28.1 IC14.10 IC14.17 PJ14.2 Q28.1 Q28.2 Q28.3 R203.1 R207.1 R215.1 R225.1 R229.1 ; off-sheet GND_14
SIGN1886: IC14.9 R206.2
SIGN1889: C238.2 C240.1 IC13.6 R222.1 R223.2 R226.1 R227.2
SIGN1891: C230.2 D13.A IC13.12 R200.2
SIGN1893: C233.1 D14.C R210.2
SIGN1894: C223.2 IC14.3
SIGN1895: IC14.1 R213.1
SIGN1896: C227.2 IC14.7 R199.2
SIGN1897: IC13.1 R212.1
SIGN1899: IC13.9 R204.2
SIGN1901: C222.2 IC13.3
SIGN1902: C229.2 IC14.8 IC14.14 R197.2
SIGN1906: C239.2 C241.1 IC14.6 R224.1 R225.2 R228.1 R229.2
SIGN1908: C226.2 IC13.7 R198.2
SIGN1910: C224.2 R198.1
SIGN1913: IC13.13 R214.2
SIGN1914: C235.2 C454.2 IC14.4 R217.1 R219.2
SIGN1915: C225.2 R199.1
SIGN1916: C228.2 IC13.8 IC13.14 R196.2
SIGN1920: IC14.13 R215.2
SIGN2121: IC13.11 R200.1 R201.2
SIGN2122: IC14.11 R202.1 R203.2
SIGN2135: C232.1 D13.C R208.2
SIGN2136: C231.2 D14.A IC14.12 R202.2
SIGN2270: Q25.4 R212.2
SIGN2271: Q26.4 R209.2
SIGN2272: Q28.4 R211.2
SIGN2273: Q27.4 R213.2
SIGN2274: C232.2 IC13.2 L13.2 Q25.1 Q25.2 Q25.3 Q26.5 Q26.6 Q26.7 Q26.8 R216.2
SIGN2275: C233.2 IC14.2 L14.2 Q27.1 Q27.2 Q27.3 Q28.5 Q28.6 Q28.7 Q28.8 R217.2
SIGN2314: C234.2 C452.2 IC13.4 R216.1 R218.2
VP_3R3_VOUT_13: C234.1 C240.2 C242.2 C244.2 C451.2 C499.2 C500.2 C532.2 E25.1 IC13.5 L13.1 R218.1 R222.2 R226.2 ; off-sheet VP_3R3_VOUT_13
VP_3R3_VOUT_14: C235.1 C241.2 C243.2 C245.2 C453.2 C501.2 C502.2 C533.2 E27.1 IC14.5 L14.1 R219.1 R224.2 R228.2 ; off-sheet VP_3R3_VOUT_14
VP_12R0_VIN_13: C216.2 C218.2 C220.2 C236.2 PJ13.1 Q25.5 Q25.6 Q25.7 Q25.8 R196.1 ; off-sheet VP_12R0_VIN_13
VP_12R0_VIN_14: C217.2 C219.2 C221.2 C237.2 PJ14.1 Q27.5 Q27.6 Q27.7 Q27.8 R197.1 ; off-sheet VP_12R0_VIN_14
NetIC13_15: IC13.15 R209.1
NetIC13_16: IC13.16 R208.1
NetIC14_15: IC14.15 R211.1
NetIC14_16: IC14.16 R210.1
NetR204_1: R204.1 R205.2
NetR206_1: R206.1 R207.2

Not connected (* = marked no-connect by the designer): L13 3; L14 3

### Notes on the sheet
- Unless otherwise specified
- Resistors 1/16W (1608)
- Capacitors 50V (1608)
- temperature characteristics X5R
- DC+12V
- INPUT
- (near E25) +3.3V 13A 100%LOAD
- (near E25) OUTPUT
- (near IC13) 200kHz
- (near E26) GND
- (near E27) +3.3V 13A 50%LOAD
- (near E27) OUTPUT
- (near IC14) 200kHz
- (near E28) GND

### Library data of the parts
C216 C217 = C: as C198 on sheet 8
C218-C221 = C: as C199 on sheet 8
C222-C225 C232 C233 C236 C237 = C: as C201 on sheet 8
C226 = C: SQ_PART_MODEL: CON_220p; FNPARTSNAMEG: CHIP CERAMIC CAPACITOR (1608); USEINPARTSLIST: YES; OriginalSymbolOrigin: (2540,7620); CDMASTERCADCELG: C8100E; MFSOLDERINGPROP: .; TEMPCHARACTERI2: CH; MFFORMINGDIVP: KC; OUMECLASSIFICATION: セラミックコンデンサ; SIZECODESMD: 1608; MFMOUNTSYMBOLP: 80; PCODE: P03039269127; FNCLASSCODEG: P03-03; MAXGCOUNT: 1; RATEDVOLTAGE: 50; COMPONENTNAME: GDM030000578; OUMEMAKER: KYC 京セラ; MFPACKAGEMETHOP: S; NOMINALCAPACITA: 220p; OUMEMAKERKATAMEI: CM105CH221J50AT; CAPACITANCETOLE: J
C227 = C: SQ_PART_MODEL: CON_220p; FNPARTSNAMEG: CHIP CERAMIC CAPACITOR (1608); USEINPARTSLIST: YES; OriginalSymbolOrigin: (2540,7620); MFSOLDERINGPROP: .; TEMPCHARACTERI2: CH; MFFORMINGDIVP: KC; OUMECLASSIFICATION: セラミックコンデンサ; SIZECODESMD: 1608; MFMOUNTSYMBOLP: 80; CDMASTERCADCELG: C8100E; PCODE: P03039269127; FNCLASSCODEG: P03-03; MAXGCOUNT: 1; RATEDVOLTAGE: 50; COMPONENTNAME: GDM030000578; OUMEMAKER: KYC 京セラ; MFPACKAGEMETHOP: S; NOMINALCAPACITA: 220p; OUMEMAKERKATAMEI: CM105CH221J50AT; CAPACITANCETOLE: J
C228 C229 = C: as C204 on sheet 8
C230 C231 = C: as C205 on sheet 8
C234 C235 = C: SQ_PART_MODEL: CON_470n; FNPARTSNAMEG: CHIP CERAMIC CAPACITOR (1608); USEINPARTSLIST: YES; OriginalSymbolOrigin: (2540,7620); MFSOLDERINGPROP: .; TEMPCHARACTERI2: B; MFFORMINGDIVP: KC; OUMECLASSIFICATION: セラミックコンデンサ; SIZECODESMD: 1608; MFMOUNTSYMBOLP: 80; CDMASTERCADCELG: C8100E; PCODE: P03039ABG127; FNCLASSCODEG: P03-03; MAXGCOUNT: 1; RATEDVOLTAGE: 10; COMPONENTNAME: GDM030001129; OUMEMAKER: KYC 京セラ; MFPACKAGEMETHOP: S; NOMINALCAPACITA: 470n; OUMEMAKERKATAMEI: CM105B474K10AT; CAPACITANCETOLE: K
C238-C241 = C: as C209 on sheet 8
C242 C243 = C: as C211 on sheet 8
C244 C245 = C: SQ_PART_MODEL: CON_1u; FNPARTSNAMEG: CHIP CERAMIC CAPACITOR (1608); PARTCOMMENT: 代表セル<KC0008> がフットプリントに登録されていません。; USEINPARTSLIST: YES; OriginalSymbolOrigin: (2540,7620); MFSOLDERINGPROP: .; TEMPCHARACTERI2: B; MFFORMINGDIVP: KC; OUMECLASSIFICATION: セラミックコンデンサ; SIZECODESMD: 1608; MFMOUNTSYMBOLP: 80; CDMASTERCADCELG: KC0008; PCODE: P03B000000ZQ; FNCLASSCODEG: P03-03; MAXGCOUNT: 1; RATEDVOLTAGE: 6.3; COMPONENTNAME: GDM030000202; OUMEMAKER: MRT 村田製作所; MFPACKAGEMETHOP: S; NOMINALCAPACITA: 1u; OUMEMAKERKATAMEI: GRM185B10J105KE21D; CAPACITANCETOLE: K
C451-C454 = C: as C449 on sheet 8
C499-C502 C532 C533 = C: as C497 on sheet 8
D13 D14 = D: as D12 on sheet 8
E25-E28 = EB: as E23 on sheet 8
IC13 IC14 = LTC7803UD: as IC12 on sheet 8
L13 L14 = L1C: USEINPARTSLIST: YES; PARTNAME: 7443630140; SAVECOUNT: 6; SAVEAREA0: -5636,-341,27978,18652; OriginalSymbolOrigin: (5080,15240); COMPONENTNAME: L1C_L1C; MAXGCOUNT: 1; OUMEMAKER: WURTH
PJ13 PJ14 = CN2: as PJ12 on sheet 8
Q25-Q28 = MFNKR2: USEINPARTSLIST: YES; PARTNAME: TPH6R003NL; SAVEAREA0: -9199,-39,32138,22820; TIME: 18:57:44; UPDATEUSER: q91866sr; UPDATETIME: 12:36:02; SAVECOUNT: 10; OriginalSymbolOrigin: (5080,20320); MAXGCOUNT: 1; COMPONENTNAME: MFNKR2_MFNKR2
R196 R197 = R: as R179 on sheet 8
R198 R199 = R: as R189 on sheet 8
R200 R202 = R: as R181 on sheet 8
R201 R203 = R: as R182 on sheet 8
R204 R206 = R: SQ_PART_MODEL: RES_27K; FNPARTSNAMEG: CHIP RESISTOR (1608); USEINPARTSLIST: YES; OriginalSymbolOrigin: (5080,5080); MAXGCOUNT: 1; TOLERANCE: F; COMPONENTNAME: G36010027195; MFSOLDERINGPROP: .; OUMEMAKER: NAE 松下電子部品; MFPACKAGEMETHOP: S; MFFORMINGDIVP: KC; MOUNTINGFORMSMD: SMD; OUMECLASSIFICATION: 表面実装用固定抵抗器; ASIMVALUE: 27K; MFMOUNTSYMBOLP: 80; POWERRATING: 63m; OUMEMAKERKATAMEI: ERJ3GEYF273V; NUMBEROFELEMENT: 0; VAL2: 62.5mW; CDMASTERCADCELG: DR802R; PCODE: P01042508622; FNCLASSCODEG: P01-08
R205 R207 = R: SQ_PART_MODEL: RES_160K; FNPARTSNAMEG: CHIP RESISTOR (1608); USEINPARTSLIST: YES; OriginalSymbolOrigin: (5080,5080); MAXGCOUNT: 1; COMPONENTNAME: G51011061108; MFSOLDERINGPROP: .; OUMEMAKER: HDK 北陸電気工業; MFPACKAGEMETHOP: S; MFFORMINGDIVP: KC; MOUNTINGFORMSMD: SMD; OUMECLASSIFICATION: 表面実装用固定抵抗器; RESISTANCETOLER: F; MFMOUNTSYMBOLP: 80; POWERRATING: 63m; OUMEMAKERKATAMEI: CR1/16 164FV; NOMINALRESISTAN: 160K; NUMBEROFELEMENT: 0; VAL2: 62.5mW; CDMASTERCADCELG: DR802R; PCODE: P01042125225; FNCLASSCODEG: P01-08
R208 R210 R214 R215 = R: as R185 on sheet 8
R209 R211-R213 = R: as R186 on sheet 8
R216 R217 = R: SQ_PART_MODEL: RES_3.3K; FNPARTSNAMEG: CHIP RESISTOR (1608); USEINPARTSLIST: YES; OriginalSymbolOrigin: (5080,5080); TOLERANCE: F; ASIMVALUE: 3.3K; MAXGCOUNT: 1; COMPONENTNAME: G5101105R107; MFSOLDERINGPROP: .; OUMEMAKER: ROH ロー・; MFPACKAGEMETHOP: S; MFFORMINGDIVP: KC; MOUNTINGFORMSMD: SMD; OUMECLASSIFICATION: 表面実装用固定抵抗器; MFMOUNTSYMBOLP: 80; POWERRATING: 63m; OUMEMAKERKATAMEI: MCR03EZPFX3301; NUMBEROFELEMENT: 0; VAL2: 62.5mW; CDMASTERCADCELG: DR802R; PCODE: P01042250729; FNCLASSCODEG: P01-08
R218 R219 = R: SQ_PART_MODEL: RES_68K; FNPARTSNAMEG: CHIP RESISTOR (1608); USEINPARTSLIST: YES; OriginalSymbolOrigin: (5080,5080); TOLERANCE: F; ASIMVALUE: 68K; MAXGCOUNT: 1; COMPONENTNAME: G36010027126; MFSOLDERINGPROP: .; OUMEMAKER: HDK 北陸電気工業; MFPACKAGEMETHOP: S; MFFORMINGDIVP: KC; MOUNTINGFORMSMD: SMD; OUMECLASSIFICATION: 表面実装用固定抵抗器; MFMOUNTSYMBOLP: 80; POWERRATING: 63m; OUMEMAKERKATAMEI: CR1/16 683FV; NUMBEROFELEMENT: 0; VAL2: 62.5mW; VAL1: 68K(F); CDMASTERCADCELG: DR802R; PCODE: P01042456220; FNCLASSCODEG: P01-08
R222 R224 = R: as R192 on sheet 8
R223 R225 = R: as R193 on sheet 8
R226 R228 = R: as R194 on sheet 8
R227 R229 = R: as R195 on sheet 8
U?#9 = WAKU_DEF100: PLOTTIME: HH:MM; SAVEAREA0: 330961,54,387907,31546; TIME: 19:23:07; UPDATEUSER: t5459927; UPDATETIME: 15:33:41; SAVECOUNT: 6; OriginalSymbolOrigin: (10160,284480); DESIGNED: ***

## Sheet 10.SchDoc
size 398 x 287 mm
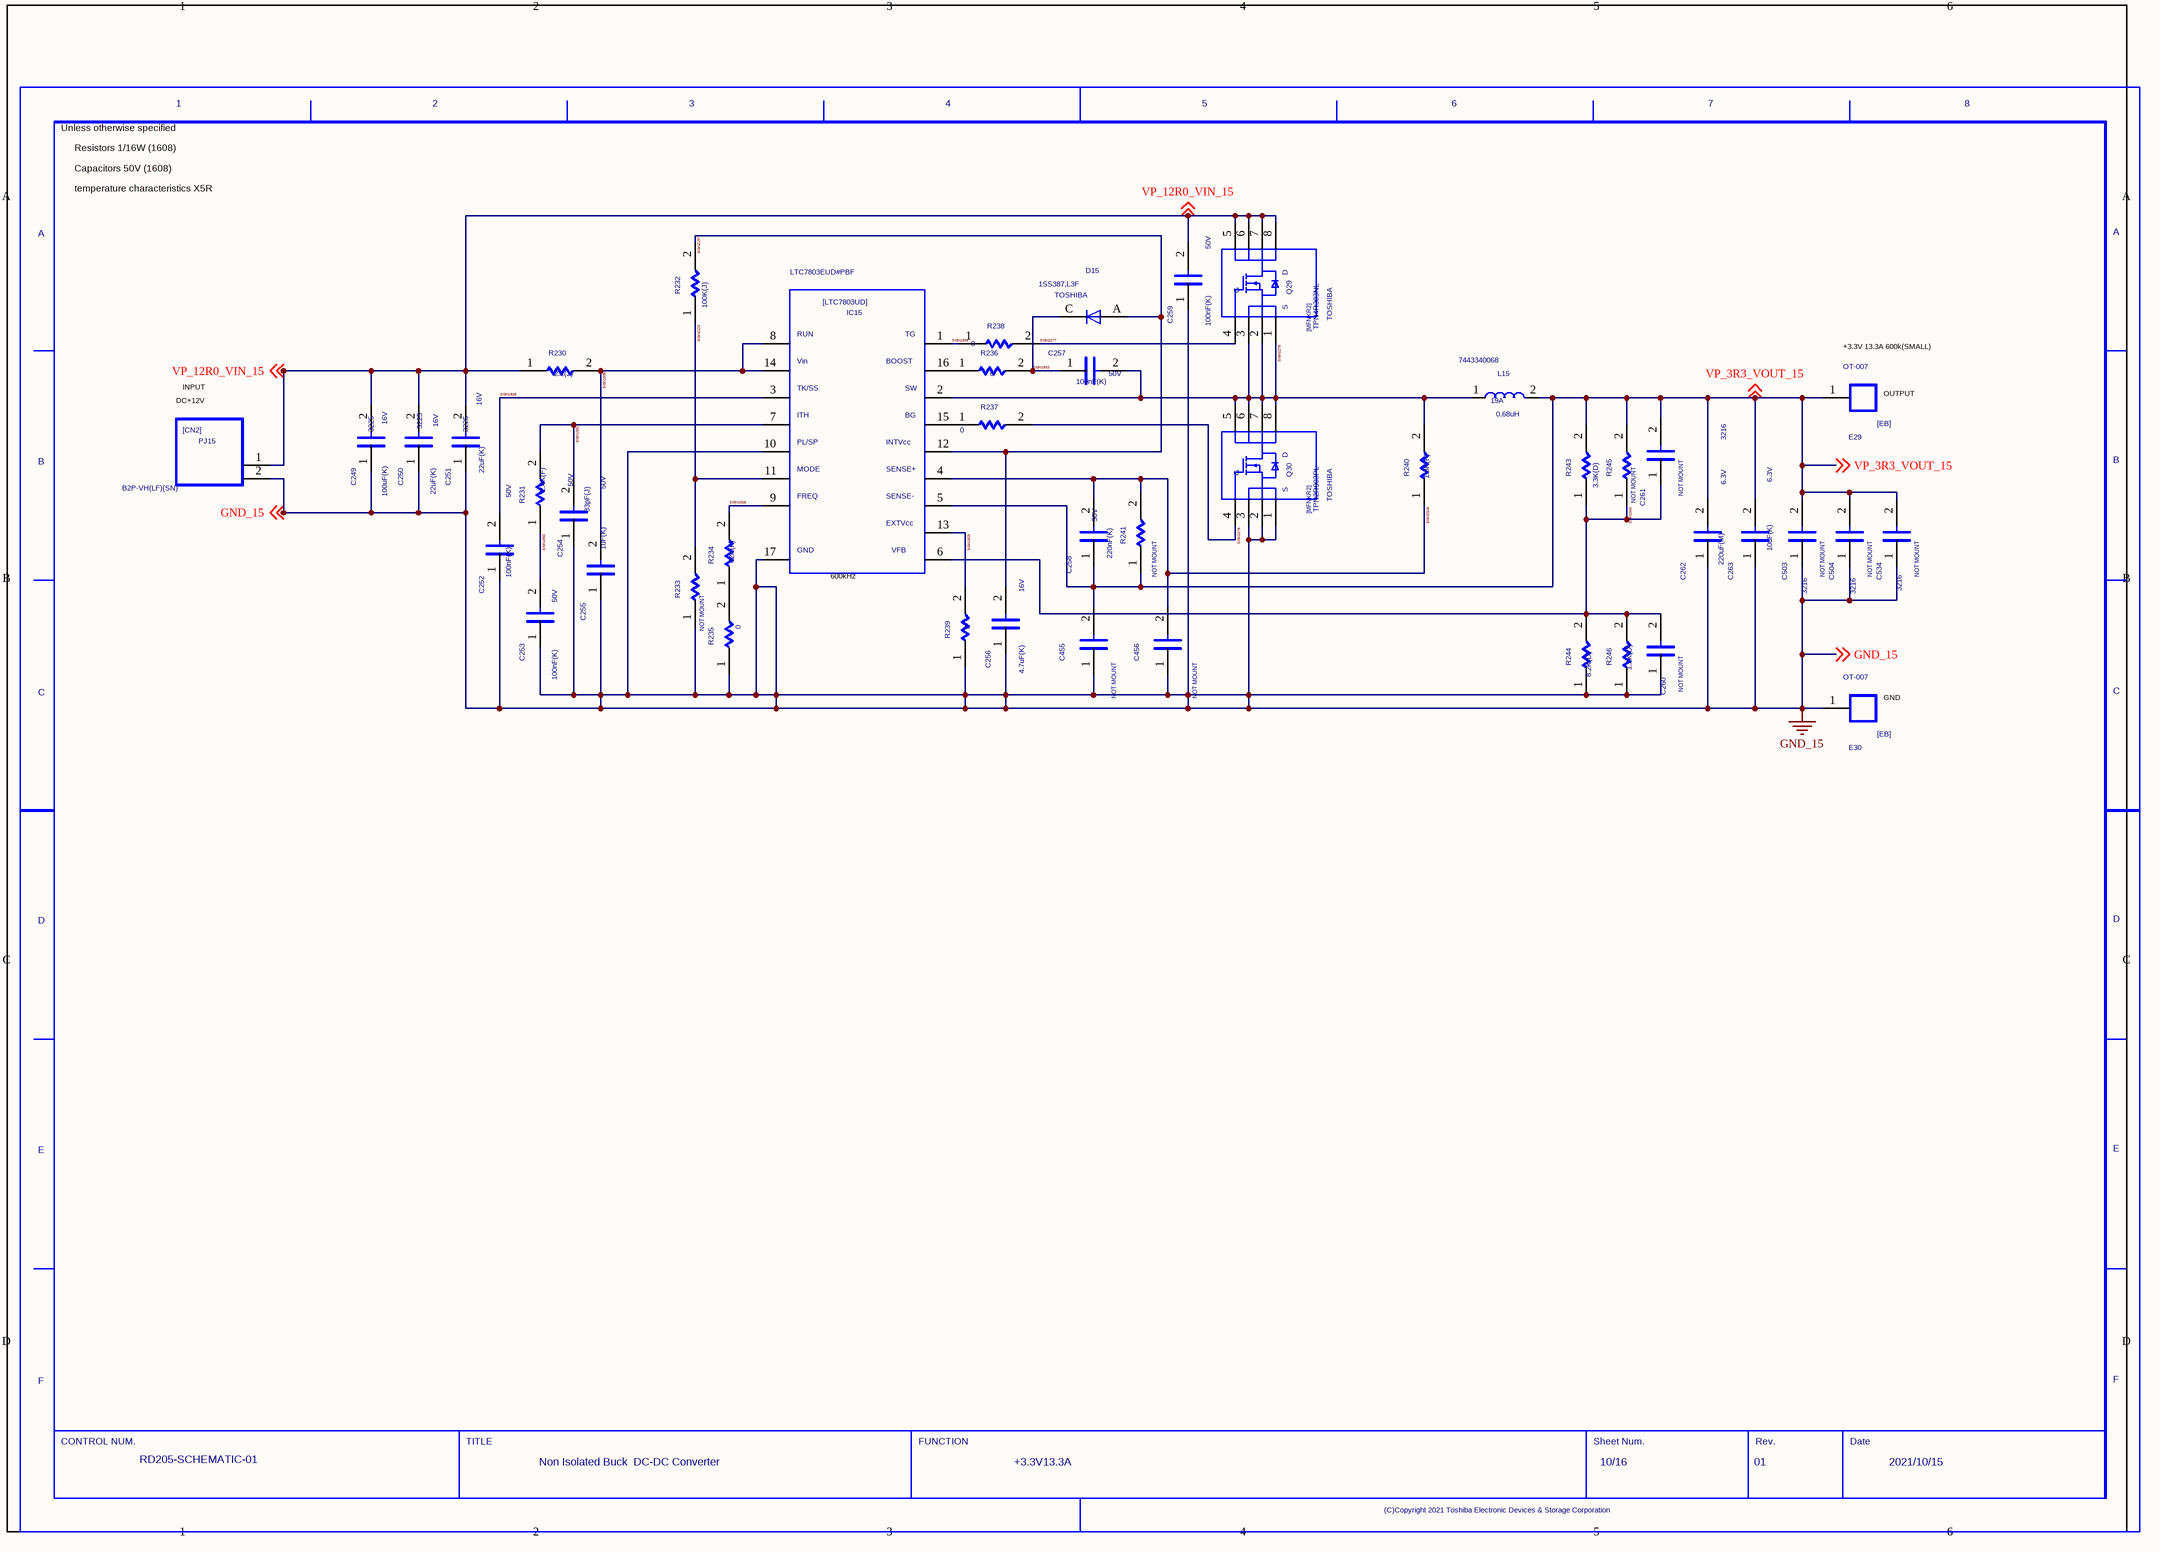
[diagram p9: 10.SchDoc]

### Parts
(Parts that share a designator on the sheet are numbered #1, #2 ... from top to bottom, then left to right.)
C249  SIZECODESMD: 3225  VAL2: 16V  VAL1: 100uF(K)  (hidden comment: C)
C250  SIZECODESMD: 3225  VAL2: 16V  VAL1: 22uF(K)  (hidden comment: C)
C251  SIZECODESMD: 3225  VAL2: 16V  VAL1: 22uF(K)  (hidden comment: C)
C252  VAL2: 50V  VAL1: 100nF(K)  (hidden comment: C)
C253  VAL2: 50V  VAL1: 100nF(K)  (hidden comment: C)
C254  VAL2: 50V  VAL1: 33pF(J)  (hidden comment: C)
C255  VAL2: 50V  VAL1: 1uF(K)  (hidden comment: C)
C256  VAL2: 16V  VAL1: 4.7uF(K)  (hidden comment: C)
C257  VAL2: 50V  VAL1: 100nF(K)  (hidden comment: C)
C258  VAL2: 50V  VAL1: 220nF(K)  (hidden comment: C)
C259  VAL2: 50V  VAL1: 100nF(K)  (hidden comment: C)
C260  NOTMOUNT: NOT MOUNT  (hidden comment: C)
C261  NOTMOUNT: NOT MOUNT  (hidden comment: C)
C262  SIZECODESMD: 3216  VAL2: 6.3V  VAL1: 220uF(M)  (hidden comment: C)
C263  VAL2: 6.3V  VAL1: 10uF(K)  (hidden comment: C)
C455  NOTMOUNT: NOT MOUNT  (hidden comment: C)
C456  NOTMOUNT: NOT MOUNT  (hidden comment: C)
C503  NOTMOUNT: NOT MOUNT  SIZECODESMD: 3216  (hidden comment: C)
C504  NOTMOUNT: NOT MOUNT  SIZECODESMD: 3216  (hidden comment: C)
C534  NOTMOUNT: NOT MOUNT  SIZECODESMD: 3216  (hidden comment: C)
D15  USERCOMPTEXT3: TOSHIBA  VAL3: 1SS387,L3F  (hidden comment: D)
E29  VAL3: OT-007  (hidden comment: EB)
E30  VAL3: OT-007  (hidden comment: EB)
IC15  VAL3: LTC7803EUD#PBF  (hidden comment: LTC7803UD)
L15  VAL3: 7443340068  VAL2: 19A  VAL1: 0.68uH  (hidden comment: L)
PJ15  VAL3: B2P-VH(LF)(SN)  (hidden comment: CN2)
Q29  USERCOMPTEXT3: TOSHIBA  VAL3: TPN4R303NL  (hidden comment: MFNKR2)
Q30  USERCOMPTEXT3: TOSHIBA  VAL3: TPN2R903PL  (hidden comment: MFNKR2)
R230  VAL1: 2.2(J)  (hidden comment: R)
R231  VAL1: 2.4K(F)  (hidden comment: R)
R232  VAL1: 100K(J)  (hidden comment: R)
R233  NOTMOUNT: NOT MOUNT  (hidden comment: R)
R234  VAL1: 62K(F)  (hidden comment: R)
R235  VAL1: 0  (hidden comment: R)
R236  VAL1: 0  (hidden comment: R)
R237  VAL1: 0  (hidden comment: R)
R238  VAL1: 0  (hidden comment: R)
R239  VAL1: 0  (hidden comment: R)
R240  VAL1: 1.8K(F)  (hidden comment: R)
R241  NOTMOUNT: NOT MOUNT  (hidden comment: R)
R243  VAL1: 3.3K(D)  (hidden comment: R)
R244  VAL1: 8.2K(D)  (hidden comment: R)
R245  NOTMOUNT: NOT MOUNT  (hidden comment: R)
R246  VAL1: 1.2K(D)  (hidden comment: R)
U?#10  DATE: 2021/10/15  SHEETNUMBER: 10/16  TITLE: Non Isolated Buck / DC-DC Converter  REVISION: 01  DRAWINGNUMBER: RD205-SCHEMATIC-01  FUNCTION: +3.3V13.3A  (hidden comment: WAKU_DEF100)

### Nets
GND_15: C249.1 C250.1 C251.1 C252.1 C253.1 C254.1 C255.1 C256.1 C259.1 C260.1 C262.1 C263.1 C455.1 C456.1 C503.1 C504.1 C534.1 E30.1 IC15.10 IC15.17 PJ15.2 Q30.1 Q30.2 Q30.3 R233.1 R235.1 R239.1 R244.1 R246.1 ; off-sheet GND_15
SIGN1928: C252.2 IC15.3
SIGN1929: IC15.13 R239.2
SIGN1931: C254.2 IC15.7 R231.2
SIGN1932: C253.2 R231.1
SIGN1933: C257.1 D15.C R236.2
SIGN1935: IC15.1 R238.1
SIGN1936: C255.2 IC15.8 IC15.14 R230.2
SIGN1938: IC15.9 R234.2
SIGN1940: C260.2 C261.1 IC15.6 R243.1 R244.2 R245.1 R246.2
SIGN2123: IC15.11 R232.1 R233.2
SIGN2137: C256.2 D15.A IC15.12 R232.2
SIGN2276: Q30.4 R237.2
SIGN2277: Q29.4 R238.2
SIGN2278: C257.2 IC15.2 L15.1 Q29.1 Q29.2 Q29.3 Q30.5 Q30.6 Q30.7 Q30.8 R240.2
SIGN2315: C258.2 C456.2 IC15.4 R240.1 R241.2
VP_3R3_VOUT_15: C258.1 C261.2 C262.2 C263.2 C455.2 C503.2 C504.2 C534.2 E29.1 IC15.5 L15.2 R241.1 R243.2 R245.2 ; off-sheet VP_3R3_VOUT_15
VP_12R0_VIN_15: C249.2 C250.2 C251.2 C259.2 PJ15.1 Q29.5 Q29.6 Q29.7 Q29.8 R230.1 ; off-sheet VP_12R0_VIN_15
NetIC15_15: IC15.15 R237.1
NetIC15_16: IC15.16 R236.1
NetR234_1: R234.1 R235.2

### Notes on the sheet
- Unless otherwise specified
- Resistors 1/16W (1608)
- Capacitors 50V (1608)
- temperature characteristics X5R
- DC+12V
- INPUT
- (near E29) +3.3V 13.3A 600k(SMALL)
- (near E29) OUTPUT
- (near IC15) 600kHz
- (near E30) GND

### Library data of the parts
C249 = C: as C198 on sheet 8
C250 C251 = C: as C199 on sheet 8
C252 C253 C257 C259 = C: as C201 on sheet 8
C254 = C: SQ_PART_MODEL: CON_33p; FNPARTSNAMEG: CHIP CERAMIC CAPACITOR (1608); USEINPARTSLIST: YES; OriginalSymbolOrigin: (2540,7620); TOLERANCE: J; ASIMVALUE: 33P; CDMASTERCADCELG: C8100E; MFSOLDERINGPROP: .; TEMPCHARACTERI2: CH; MFFORMINGDIVP: KC; OUMECLASSIFICATION: セラミックコンデンサ; SIZECODESMD: 1608; MFMOUNTSYMBOLP: 80; PCODE: P03039307126; FNCLASSCODEG: P03-03; MAXGCOUNT: 1; RATEDVOLTAGE: 50; COMPONENTNAME: G36030011181; OUMEMAKER: KYC 京セラ; MFPACKAGEMETHOP: S; OUMEMAKERKATAMEI: CM105CH330J50AT
C255 = C: as C204 on sheet 8
C256 = C: as C205 on sheet 8
C258 = C: as C207 on sheet 8
C260 C261 = C: as C209 on sheet 8
C262 = C: as C211 on sheet 8
C263 = C: as C212 on sheet 8
C455 C456 = C: as C449 on sheet 8
C503 C504 C534 = C: as C497 on sheet 8
D15 = D: as D12 on sheet 8
E29 E30 = EB: as E23 on sheet 8
IC15 = LTC7803UD: as IC12 on sheet 8
L15 = L: as L12 on sheet 8
PJ15 = CN2: as PJ12 on sheet 8
Q29 Q30 = MFNKR2: as Q23 on sheet 8
R230 = R: as R179 on sheet 8
R231 = R: SQ_PART_MODEL: RES_2.4K; FNPARTSNAMEG: CHIP RESISTOR (1608); USEINPARTSLIST: YES; OriginalSymbolOrigin: (5080,5080); TOLERANCE: F; ASIMVALUE: 2.4K; MAXGCOUNT: 1; COMPONENTNAME: G36010104094; MFSOLDERINGPROP: .; OUMEMAKER: KAM 釜屋電機; MFPACKAGEMETHOP: S; MFFORMINGDIVP: KC; MOUNTINGFORMSMD: SMD; OUMECLASSIFICATION: 表面実装用固定抵抗器; MFMOUNTSYMBOLP: 80; POWERRATING: 63m; OUMEMAKERKATAMEI: RMC1/16-242FTP; NUMBEROFELEMENT: 0; VAL2: 62.5mW; CDMASTERCADCELG: DR802R; PCODE: P01042166327; FNCLASSCODEG: P01-08
R232 = R: as R181 on sheet 8
R233 = R: as R182 on sheet 8
R234 = R: as R183 on sheet 8
R235 = R: as R184 on sheet 8
R236 R239 = R: as R185 on sheet 8
R237 R238 = R: as R186 on sheet 8
R240 = R: SQ_PART_MODEL: RES_1.8K; FNPARTSNAMEG: CHIP RESISTOR (1608); USEINPARTSLIST: YES; OriginalSymbolOrigin: (5080,5080); TOLERANCE: F; ASIMVALUE: 1.8K; MAXGCOUNT: 1; COMPONENTNAME: G36010104056; MFSOLDERINGPROP: .; OUMEMAKER: HDK 北陸電気工業; MFPACKAGEMETHOP: S; MFFORMINGDIVP: KC; MOUNTINGFORMSMD: SMD; OUMECLASSIFICATION: 表面実装用固定抵抗器; MFMOUNTSYMBOLP: 80; POWERRATING: 63m; OUMEMAKERKATAMEI: CR1/16 182FV; NUMBEROFELEMENT: 0; VAL2: 62.5mW; CDMASTERCADCELG: DR802R; PCODE: P01042030222; FNCLASSCODEG: P01-08
R241 = R: SQ_PART_MODEL: RES_22K; FNPARTSNAMEG: CHIP RESISTOR (1608); USEINPARTSLIST: YES; OriginalSymbolOrigin: (5080,5080); MAXGCOUNT: 1; COMPONENTNAME: G36010027089; OUMEMAKER: KOA ＫＯＡ; MOUNTINGFORMSMD: SMD; OUMECLASSIFICATION: 表面実装用固定抵抗器; RESISTANCETOLER: F; POWERRATING: 63m; OUMEMAKERKATAMEI: RK73H1JTD2202F; NOMINALRESISTAN: 22K; CDMASTERCADCELG: DR802R; MFSOLDERINGPROP: .; MFPACKAGEMETHOP: S; MFFORMINGDIVP: KC; MFMOUNTSYMBOLP: 80; NUMBEROFELEMENT: 0; VAL2: 62.5mW; VAL1: 22K(F); PCODE: P01042207426; FNCLASSCODEG: P01-08
R243 = R: as R192 on sheet 8
R244 = R: as R193 on sheet 8
R245 = R: as R194 on sheet 8
R246 = R: as R195 on sheet 8
U?#10 = WAKU_DEF100: as U?#9 on sheet 9

## Sheet 11.SchDoc
size 398 x 287 mm
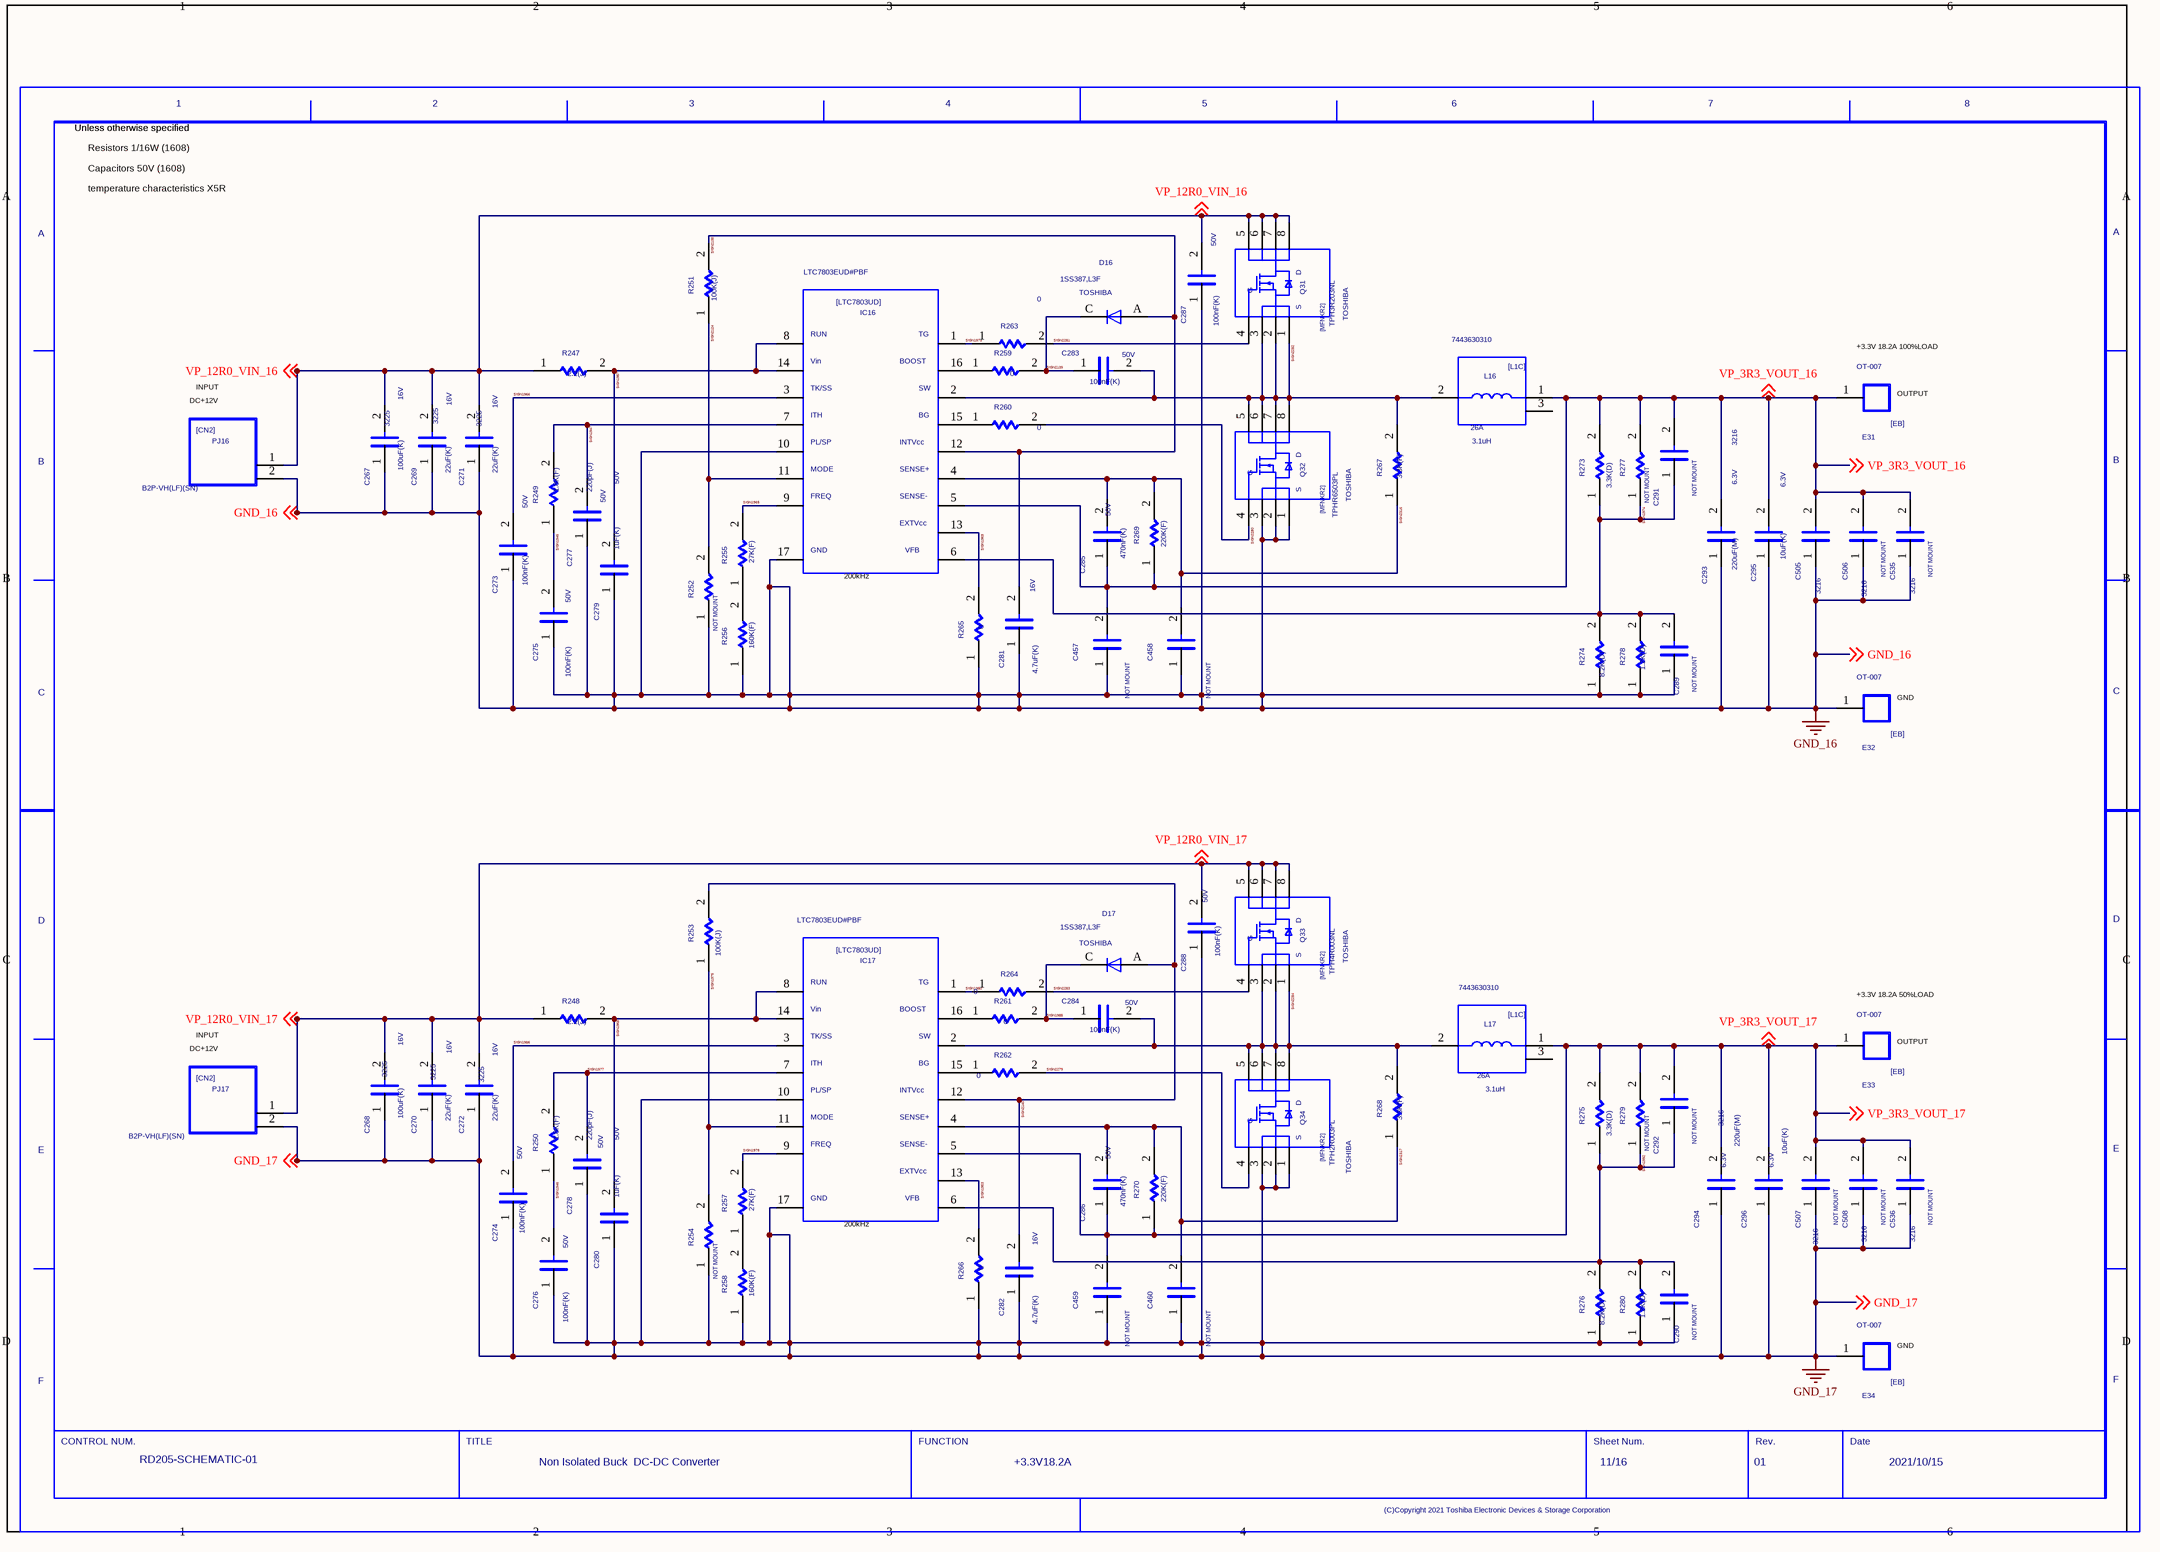
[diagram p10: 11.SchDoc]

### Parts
(Parts that share a designator on the sheet are numbered #1, #2 ... from top to bottom, then left to right.)
C267  SIZECODESMD: 3225  VAL2: 16V  VAL1: 100uF(K)  (hidden comment: C)
C268  SIZECODESMD: 3225  VAL2: 16V  VAL1: 100uF(K)  (hidden comment: C)
C269  SIZECODESMD: 3225  VAL2: 16V  VAL1: 22uF(K)  (hidden comment: C)
C270  SIZECODESMD: 3225  VAL2: 16V  VAL1: 22uF(K)  (hidden comment: C)
C271  SIZECODESMD: 3225  VAL2: 16V  VAL1: 22uF(K)  (hidden comment: C)
C272  SIZECODESMD: 3225  VAL2: 16V  VAL1: 22uF(K)  (hidden comment: C)
C273  VAL2: 50V  VAL1: 100nF(K)  (hidden comment: C)
C274  VAL2: 50V  VAL1: 100nF(K)  (hidden comment: C)
C275  VAL2: 50V  VAL1: 100nF(K)  (hidden comment: C)
C276  VAL2: 50V  VAL1: 100nF(K)  (hidden comment: C)
C277  VAL2: 50V  VAL1: 220pF(J)  (hidden comment: C)
C278  VAL2: 50V  VAL1: 220pF(J)  (hidden comment: C)
C279  VAL2: 50V  VAL1: 1uF(K)  (hidden comment: C)
C280  VAL2: 50V  VAL1: 1uF(K)  (hidden comment: C)
C281  VAL2: 16V  VAL1: 4.7uF(K)  (hidden comment: C)
C282  VAL2: 16V  VAL1: 4.7uF(K)  (hidden comment: C)
C283  VAL2: 50V  VAL1: 100nF(K)  (hidden comment: C)
C284  VAL2: 50V  VAL1: 100nF(K)  (hidden comment: C)
C285  VAL2: 50V  VAL1: 470nF(K)  (hidden comment: C)
C286  VAL2: 50V  VAL1: 470nF(K)  (hidden comment: C)
C287  VAL2: 50V  VAL1: 100nF(K)  (hidden comment: C)
C288  VAL2: 50V  VAL1: 100nF(K)  (hidden comment: C)
C289  NOTMOUNT: NOT MOUNT  (hidden comment: C)
C290  NOTMOUNT: NOT MOUNT  (hidden comment: C)
C291  NOTMOUNT: NOT MOUNT  (hidden comment: C)
C292  NOTMOUNT: NOT MOUNT  (hidden comment: C)
C293  SIZECODESMD: 3216  VAL2: 6.3V  VAL1: 220uF(M)  (hidden comment: C)
C294  SIZECODESMD: 3216  VAL2: 6.3V  VAL1: 220uF(M)  (hidden comment: C)
C295  VAL2: 6.3V  VAL1: 10uF(K)  (hidden comment: C)
C296  VAL2: 6.3V  VAL1: 10uF(K)  (hidden comment: C)
C457  NOTMOUNT: NOT MOUNT  (hidden comment: C)
C458  NOTMOUNT: NOT MOUNT  (hidden comment: C)
C459  NOTMOUNT: NOT MOUNT  (hidden comment: C)
C460  NOTMOUNT: NOT MOUNT  (hidden comment: C)
C505  SIZECODESMD: 3216  (hidden comment: C)
C506  NOTMOUNT: NOT MOUNT  SIZECODESMD: 3216  (hidden comment: C)
C507  NOTMOUNT: NOT MOUNT  SIZECODESMD: 3216  (hidden comment: C)
C508  NOTMOUNT: NOT MOUNT  SIZECODESMD: 3216  (hidden comment: C)
C535  NOTMOUNT: NOT MOUNT  SIZECODESMD: 3216  (hidden comment: C)
C536  NOTMOUNT: NOT MOUNT  SIZECODESMD: 3216  (hidden comment: C)
D16  COMPCOMMENT: TOSHIBA  VAL3: 1SS387,L3F  (hidden comment: D)
D17  USERCOMPTEXT3: TOSHIBA  VAL3: 1SS387,L3F  (hidden comment: D)
E31  VAL3: OT-007  (hidden comment: EB)
E32  VAL3: OT-007  (hidden comment: EB)
E33  VAL3: OT-007  (hidden comment: EB)
E34  VAL3: OT-007  (hidden comment: EB)
IC16  VAL3: LTC7803EUD#PBF  (hidden comment: LTC7803UD)
IC17  VAL3: LTC7803EUD#PBF  (hidden comment: LTC7803UD)
L16  VAL3: 7443630310  VAL2: 26A  VAL1: 3.1uH  (hidden comment: L1C)
L17  VAL3: 7443630310  VAL2: 26A  VAL1: 3.1uH  (hidden comment: L1C)
PJ16  VAL3: B2P-VH(LF)(SN)  (hidden comment: CN2)
PJ17  VAL3: B2P-VH(LF)(SN)  (hidden comment: CN2)
Q31  USERCOMPTEXT3: TOSHIBA  VAL3: TPH3R203NL  (hidden comment: MFNKR2)
Q32  USERCOMPTEXT3: TOSHIBA  VAL3: TPHR6503PL  (hidden comment: MFNKR2)
Q33  USERCOMPTEXT3: TOSHIBA  VAL3: TPH4R003NL  (hidden comment: MFNKR2)
Q34  USERCOMPTEXT3: TOSHIBA  VAL3: TPH2R003PL  (hidden comment: MFNKR2)
R247  VAL1: 2.2(J)  (hidden comment: R)
R248  VAL1: 2.2(J)  (hidden comment: R)
R249  VAL1: 1.8K(F)  (hidden comment: R)
R250  VAL1: 1.8K(F)  (hidden comment: R)
R251  VAL1: 100K(J)  (hidden comment: R)
R252  NOTMOUNT: NOT MOUNT  (hidden comment: R)
R253  VAL1: 100K(J)  (hidden comment: R)
R254  NOTMOUNT: NOT MOUNT  (hidden comment: R)
R255  VAL1: 27K(F)  (hidden comment: R)
R256  VAL1: 160K(F)  (hidden comment: R)
R257  VAL1: 27K(F)  (hidden comment: R)
R258  VAL1: 160K(F)  (hidden comment: R)
R259  VAL1: 0  (hidden comment: R)
R260  VAL1: 0  (hidden comment: R)
R261  VAL1: 0  (hidden comment: R)
R262  VAL1: 0  (hidden comment: R)
R263  VAL1: 0  (hidden comment: R)
R264  VAL1: 0  (hidden comment: R)
R265  VAL1: 0  (hidden comment: R)
R266  VAL1: 0  (hidden comment: R)
R267  VAL1: 3.3K(F)  (hidden comment: R)
R268  VAL1: 3.3K(F)  (hidden comment: R)
R269  VAL1: 220K(F)  (hidden comment: R)
R270  VAL1: 220K(F)  (hidden comment: R)
R273  VAL1: 3.3K(D)  (hidden comment: R)
R274  VAL1: 8.2K(D)  (hidden comment: R)
R275  VAL1: 3.3K(D)  (hidden comment: R)
R276  VAL1: 8.2K(D)  (hidden comment: R)
R277  NOTMOUNT: NOT MOUNT  (hidden comment: R)
R278  VAL1: 1.2K(D)  (hidden comment: R)
R279  NOTMOUNT: NOT MOUNT  (hidden comment: R)
R280  VAL1: 1.2K(D)  (hidden comment: R)
U?#11  DATE: 2021/10/15  SHEETNUMBER: 11/16  TITLE: Non Isolated Buck / DC-DC Converter  REVISION: 01  DRAWINGNUMBER: RD205-SCHEMATIC-01  FUNCTION: +3.3V18.2A  (hidden comment: WAKU_DEF100)

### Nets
GND_16: C267.1 C269.1 C271.1 C273.1 C275.1 C277.1 C279.1 C281.1 C287.1 C289.1 C293.1 C295.1 C457.1 C458.1 C505.1 C506.1 C535.1 E32.1 IC16.10 IC16.17 PJ16.2 Q32.1 Q32.2 Q32.3 R252.1 R256.1 R265.1 R274.1 R278.1 ; off-sheet GND_16
GND_17: C268.1 C270.1 C272.1 C274.1 C276.1 C278.1 C280.1 C282.1 C288.1 C290.1 C294.1 C296.1 C459.1 C460.1 C507.1 C508.1 C536.1 E34.1 IC17.10 IC17.17 PJ17.2 Q34.1 Q34.2 Q34.3 R254.1 R258.1 R266.1 R276.1 R280.1 ; off-sheet GND_17
SIGN1945: C275.2 R249.1
SIGN1946: C276.2 R250.1
SIGN1947: C277.2 IC16.7 R249.2
SIGN1953: IC17.13 R266.2
SIGN1957: C279.2 IC16.8 IC16.14 R247.2
SIGN1965: IC16.9 R255.2
SIGN1966: C273.2 IC16.3
SIGN1968: C280.2 IC17.8 IC17.14 R248.2
SIGN1969: IC16.13 R265.2
SIGN1973: IC16.1 R263.1
SIGN1974: C289.2 C291.1 IC16.6 R273.1 R274.2 R277.1 R278.2
SIGN1975: IC17.11 R253.1 R254.2
SIGN1977: C278.2 IC17.7 R250.2
SIGN1978: IC17.9 R257.2
SIGN1980: IC17.1 R264.1
SIGN1985: C284.1 D17.C R261.2
SIGN1986: C274.2 IC17.3
SIGN1992: C290.2 C292.1 IC17.6 R275.1 R276.2 R279.1 R280.2
SIGN2124: IC16.11 R251.1 R252.2
SIGN2138: C281.2 D16.A IC16.12 R251.2
SIGN2139: C283.1 D16.C R259.2
SIGN2140: C282.2 D17.A IC17.12 R253.2
SIGN2279: Q34.4 R262.2
SIGN2280: Q32.4 R260.2
SIGN2281: Q31.4 R263.2
SIGN2282: C283.2 IC16.2 L16.2 Q31.1 Q31.2 Q31.3 Q32.5 Q32.6 Q32.7 Q32.8 R267.2
SIGN2283: Q33.4 R264.2
SIGN2284: C284.2 IC17.2 L17.2 Q33.1 Q33.2 Q33.3 Q34.5 Q34.6 Q34.7 Q34.8 R268.2
SIGN2316: C285.2 C458.2 IC16.4 R267.1 R269.2
SIGN2317: C286.2 C460.2 IC17.4 R268.1 R270.2
VP_3R3_VOUT_16: C285.1 C291.2 C293.2 C295.2 C457.2 C505.2 C506.2 C535.2 E31.1 IC16.5 L16.1 R269.1 R273.2 R277.2 ; off-sheet VP_3R3_VOUT_16
VP_3R3_VOUT_17: C286.1 C292.2 C294.2 C296.2 C459.2 C507.2 C508.2 C536.2 E33.1 IC17.5 L17.1 R270.1 R275.2 R279.2 ; off-sheet VP_3R3_VOUT_17
VP_12R0_VIN_16: C267.2 C269.2 C271.2 C287.2 PJ16.1 Q31.5 Q31.6 Q31.7 Q31.8 R247.1 ; off-sheet VP_12R0_VIN_16
VP_12R0_VIN_17: C268.2 C270.2 C272.2 C288.2 PJ17.1 Q33.5 Q33.6 Q33.7 Q33.8 R248.1 ; off-sheet VP_12R0_VIN_17
NetIC16_15: IC16.15 R260.1
NetIC16_16: IC16.16 R259.1
NetIC17_15: IC17.15 R262.1
NetIC17_16: IC17.16 R261.1
NetR255_1: R255.1 R256.2
NetR257_1: R257.1 R258.2

Not connected (* = marked no-connect by the designer): L16 3; L17 3

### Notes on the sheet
- Unless otherwise specified
- Resistors 1/16W (1608)
- Capacitors 50V (1608)
- temperature characteristics X5R
- DC+12V
- INPUT
- (near E31) +3.3V 18.2A 100%LOAD
- (near E31) OUTPUT
- (near IC16) 200kHz
- (near E32) GND
- (near E33) +3.3V 18.2A 50%LOAD
- (near E33) OUTPUT
- (near IC17) 200kHz
- (near E34) GND

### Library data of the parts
C267 C268 = C: as C198 on sheet 8
C269-C272 = C: as C199 on sheet 8
C273-C276 C283 C284 C287 C288 = C: as C201 on sheet 8
C277 C278 = C: as C226 on sheet 9
C279 C280 = C: as C204 on sheet 8
C281 C282 = C: as C205 on sheet 8
C285 C286 = C: as C234 on sheet 9
C289-C292 = C: as C209 on sheet 8
C293 C294 = C: as C211 on sheet 8
C295 C296 = C: as C244 on sheet 9
C457-C460 = C: as C449 on sheet 8
C505 = C: SQ_PART_MODEL: CON_22u; FNPARTSNAMEG: CHIP CERAMIC CAPACITOR (3216); USEINPARTSLIST: YES; OriginalSymbolOrigin: (2540,7620); NOTMOUNT: NOT MOUNT; MFSOLDERINGPROP: .; TEMPCHARACTERI2: B; MFFORMINGDIVP: KC; OUMECLASSIFICATION: セラミックコンデンサ; MFMOUNTSYMBOLP: 80; CDMASTERCADCELG: DC901A; PCODE: P03B0000004V; FNCLASSCODEG: P03-03; MAXGCOUNT: 1; RATEDVOLTAGE: 6.3; COMPONENTNAME: GDM030000020; OUMEMAKER: KYC 京セラ; MFPACKAGEMETHOP: S; NOMINALCAPACITA: 22u; OUMEMAKERKATAMEI: CM316B226M06AT; VAL2: 6.3V; VAL1: 22uF(M); CAPACITANCETOLE: M
C506-C508 C535 C536 = C: as C497 on sheet 8
D16 D17 = D: as D12 on sheet 8
E31-E34 = EB: as E23 on sheet 8
IC16 IC17 = LTC7803UD: as IC12 on sheet 8
L16 L17 = L1C: as L13 on sheet 9
PJ16 PJ17 = CN2: as PJ12 on sheet 8
Q31-Q34 = MFNKR2: as Q25-Q28 on sheet 9
R247 R248 = R: as R179 on sheet 8
R249 R250 = R: as R240 on sheet 10
R251 R253 = R: as R181 on sheet 8
R252 R254 = R: as R182 on sheet 8
R255 R257 = R: as R204 on sheet 9
R256 R258 = R: as R205 on sheet 9
R259 R261 R265 R266 = R: as R185 on sheet 8
R260 R262-R264 = R: as R186 on sheet 8
R267 R268 = R: as R216 on sheet 9
R269 R270 = R: SQ_PART_MODEL: RES_220K; FNPARTSNAMEG: CHIP RESISTOR (1608); USEINPARTSLIST: YES; OriginalSymbolOrigin: (5080,5080); MAXGCOUNT: 1; COMPONENTNAME: G51011062105; MFSOLDERINGPROP: .; OUMEMAKER: NAE 松下電子部品; MFPACKAGEMETHOP: S; MFFORMINGDIVP: KC; MOUNTINGFORMSMD: SMD; OUMECLASSIFICATION: 表面実装用固定抵抗器; RESISTANCETOLER: F; MFMOUNTSYMBOLP: 80; POWERRATING: 63m; OUMEMAKERKATAMEI: ERJ3GEYF224V; NOMINALRESISTAN: 220K; NUMBEROFELEMENT: 0; VAL2: 62.5mW; CDMASTERCADCELG: DR802R; PCODE: P01042202629; FNCLASSCODEG: P01-08
R273 R275 = R: as R192 on sheet 8
R274 R276 = R: as R193 on sheet 8
R277 R279 = R: as R194 on sheet 8
R278 R280 = R: as R195 on sheet 8
U?#11 = WAKU_DEF100: as U?#9 on sheet 9

## Sheet 12.SchDoc
size 398 x 287 mm
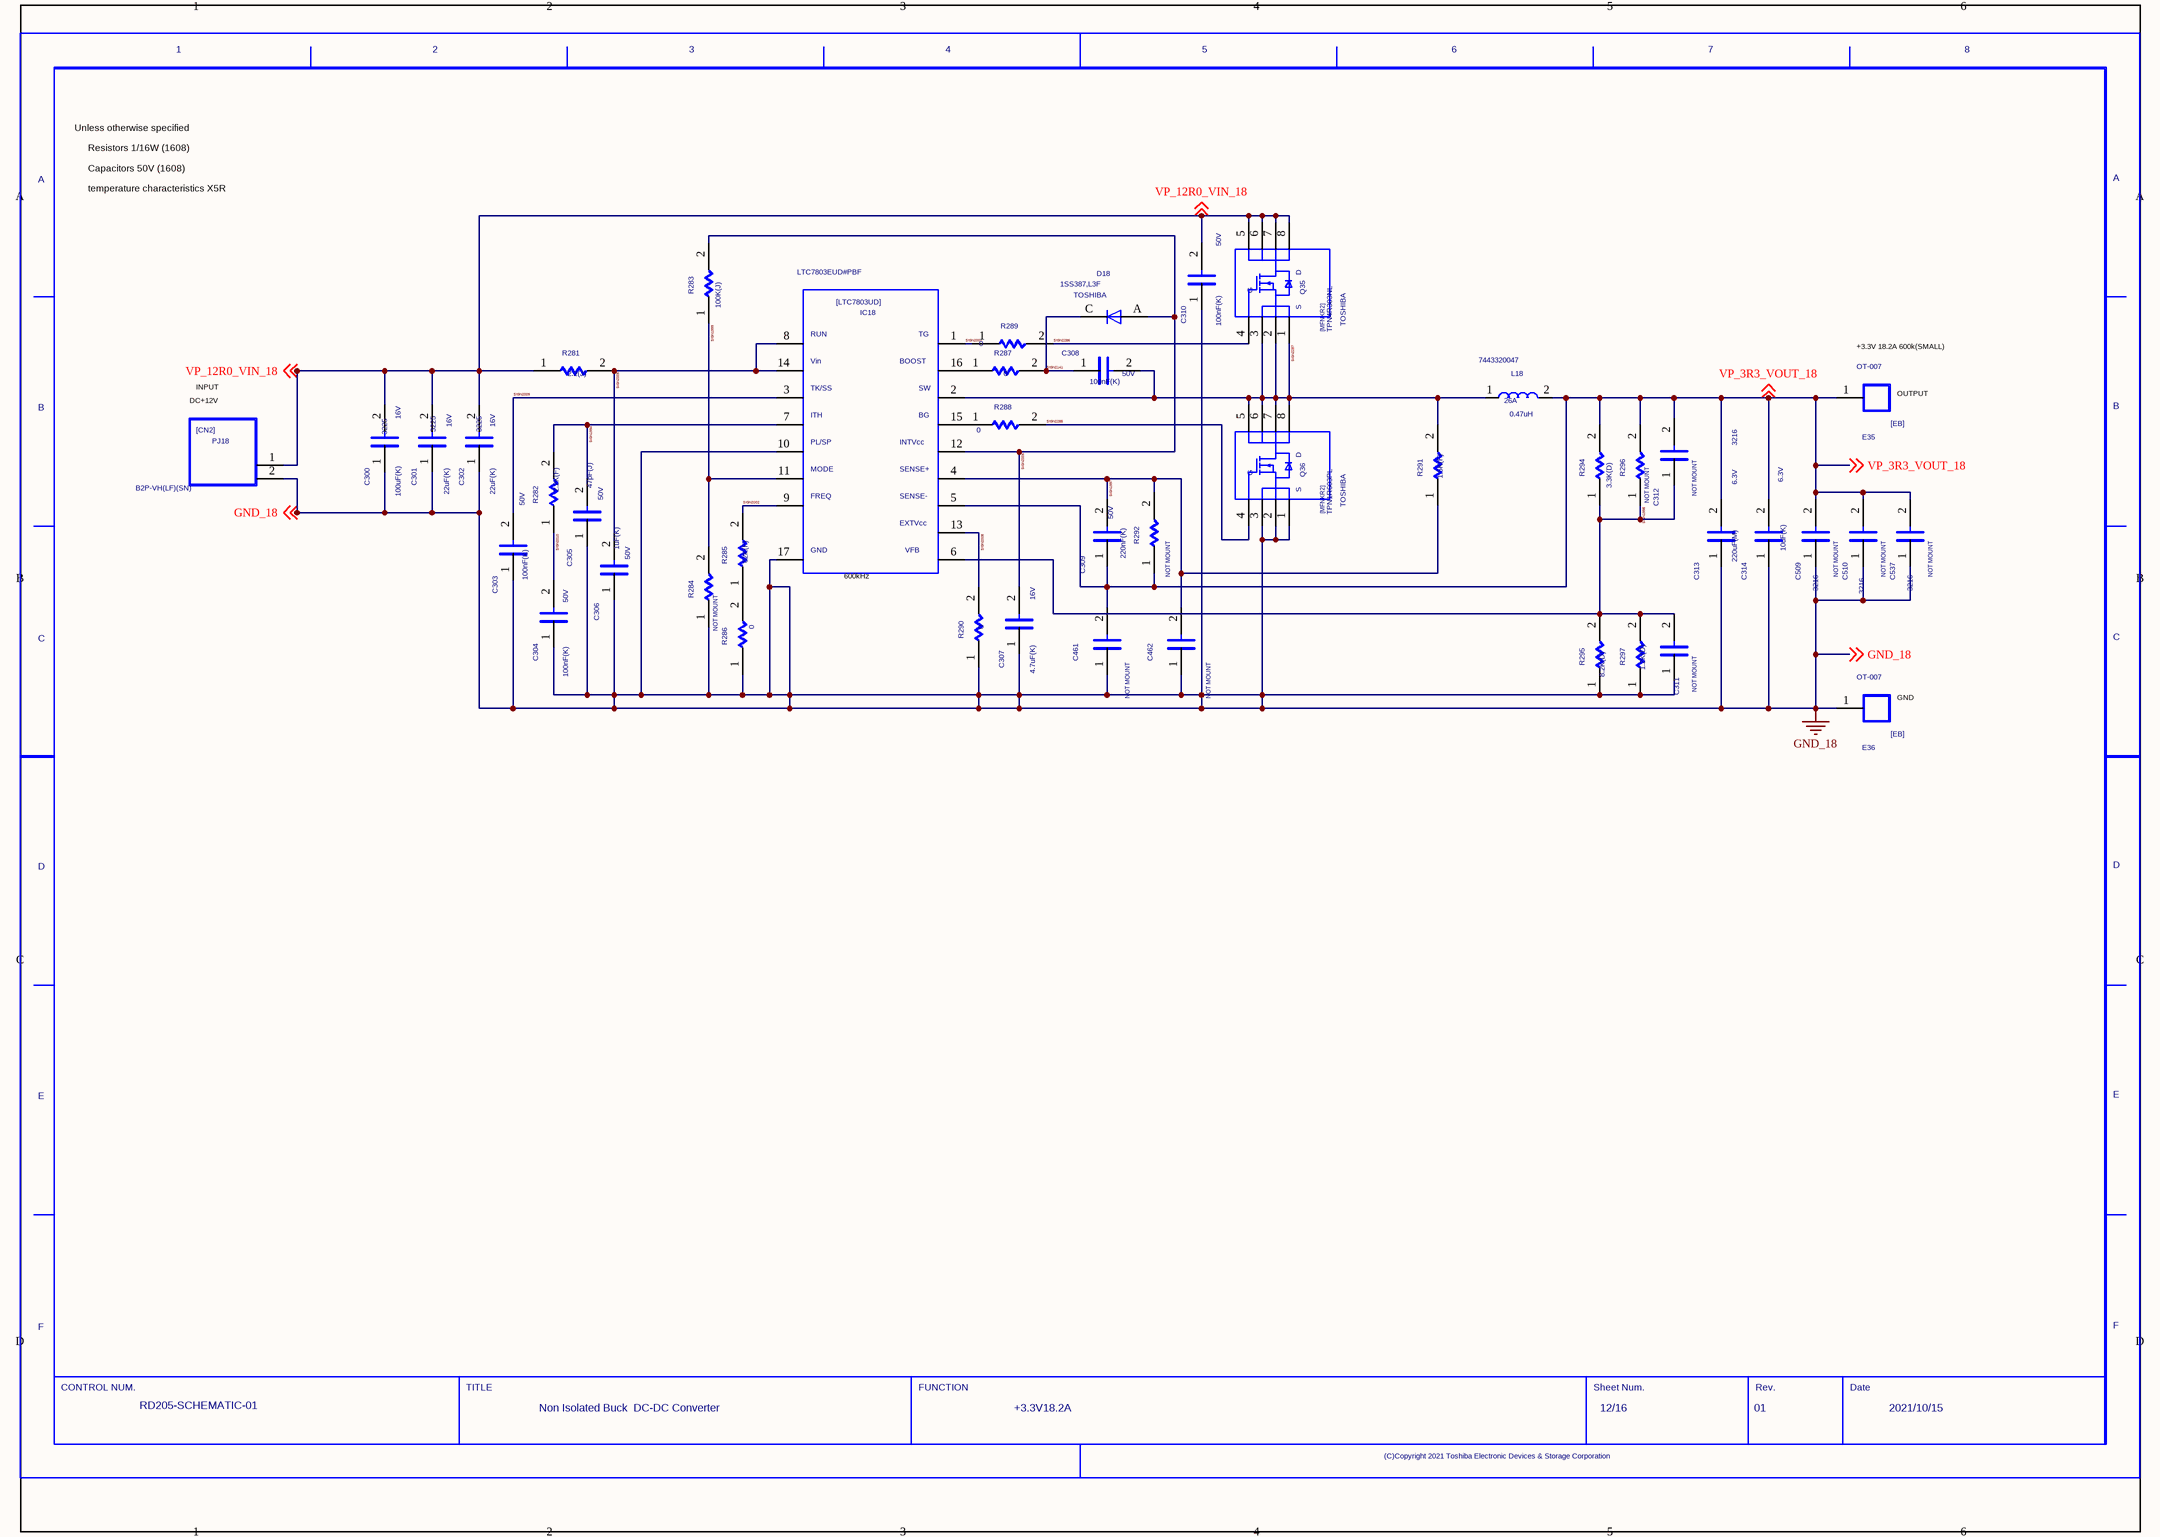
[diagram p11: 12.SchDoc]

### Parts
(Parts that share a designator on the sheet are numbered #1, #2 ... from top to bottom, then left to right.)
C300  SIZECODESMD: 3225  VAL2: 16V  VAL1: 100uF(K)  (hidden comment: C)
C301  SIZECODESMD: 3225  VAL2: 16V  VAL1: 22uF(K)  (hidden comment: C)
C302  SIZECODESMD: 3225  VAL2: 16V  VAL1: 22uF(K)  (hidden comment: C)
C303  VAL2: 50V  VAL1: 100nF(K)  (hidden comment: C)
C304  VAL2: 50V  VAL1: 100nF(K)  (hidden comment: C)
C305  VAL2: 50V  VAL1: 47pF(J)  (hidden comment: C)
C306  VAL2: 50V  VAL1: 1uF(K)  (hidden comment: C)
C307  VAL2: 16V  VAL1: 4.7uF(K)  (hidden comment: C)
C308  VAL2: 50V  VAL1: 100nF(K)  (hidden comment: C)
C309  VAL2: 50V  VAL1: 220nF(K)  (hidden comment: C)
C310  VAL2: 50V  VAL1: 100nF(K)  (hidden comment: C)
C311  NOTMOUNT: NOT MOUNT  (hidden comment: C)
C312  NOTMOUNT: NOT MOUNT  (hidden comment: C)
C313  SIZECODESMD: 3216  VAL2: 6.3V  VAL1: 220uF(M)  (hidden comment: C)
C314  VAL2: 6.3V  VAL1: 10uF(K)  (hidden comment: C)
C461  NOTMOUNT: NOT MOUNT  (hidden comment: C)
C462  NOTMOUNT: NOT MOUNT  (hidden comment: C)
C509  NOTMOUNT: NOT MOUNT  SIZECODESMD: 3216  (hidden comment: C)
C510  NOTMOUNT: NOT MOUNT  SIZECODESMD: 3216  (hidden comment: C)
C537  NOTMOUNT: NOT MOUNT  SIZECODESMD: 3216  (hidden comment: C)
D18  USERCOMPTEXT3: TOSHIBA  VAL3: 1SS387,L3F  (hidden comment: D)
E35  VAL3: OT-007  (hidden comment: EB)
E36  VAL3: OT-007  (hidden comment: EB)
IC18  VAL3: LTC7803EUD#PBF  (hidden comment: LTC7803UD)
L18  VAL3: 7443320047  VAL2: 26A  VAL1: 0.47uH  (hidden comment: L)
PJ18  VAL3: B2P-VH(LF)(SN)  (hidden comment: CN2)
Q35  USERCOMPTEXT3: TOSHIBA  VAL3: TPN4R303NL  (hidden comment: MFNKR2)
Q36  USERCOMPTEXT3: TOSHIBA  VAL3: TPN1R603PL  (hidden comment: MFNKR2)
R281  VAL1: 2.2(J)  (hidden comment: R)
R282  VAL1: 2.2K(F)  (hidden comment: R)
R283  VAL1: 100K(J)  (hidden comment: R)
R284  NOTMOUNT: NOT MOUNT  (hidden comment: R)
R285  VAL1: 62K(F)  (hidden comment: R)
R286  VAL1: 0  (hidden comment: R)
R287  VAL1: 0  (hidden comment: R)
R288  VAL1: 0  (hidden comment: R)
R289  VAL1: 0  (hidden comment: R)
R290  VAL1: 0  (hidden comment: R)
R291  VAL1: 1.5K(F)  (hidden comment: R)
R292  NOTMOUNT: NOT MOUNT  (hidden comment: R)
R294  VAL1: 3.3K(D)  (hidden comment: R)
R295  VAL1: 8.2K(D)  (hidden comment: R)
R296  NOTMOUNT: NOT MOUNT  (hidden comment: R)
R297  VAL1: 1.2K(D)  (hidden comment: R)
U?#12  DATE: 2021/10/15  SHEETNUMBER: 12/16  TITLE: Non Isolated Buck / DC-DC Converter  REVISION: 01  DRAWINGNUMBER: RD205-SCHEMATIC-01  FUNCTION: +3.3V18.2A  (hidden comment: WAKU_DEF100)

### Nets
GND_18: C300.1 C301.1 C302.1 C303.1 C304.1 C305.1 C306.1 C307.1 C310.1 C311.1 C313.1 C314.1 C461.1 C462.1 C509.1 C510.1 C537.1 E36.1 IC18.10 IC18.17 PJ18.2 Q36.1 Q36.2 Q36.3 R284.1 R286.1 R290.1 R295.1 R297.1 ; off-sheet GND_18
SIGN1994: C305.2 IC18.7 R282.2
SIGN1997: C309.2 C462.2 IC18.4 R291.1 R292.2
SIGN1998: C311.2 C312.1 IC18.6 R294.1 R295.2 R296.1 R297.2
SIGN1999: IC18.11 R283.1 R284.2
SIGN2002: IC18.9 R285.2
SIGN2003: IC18.1 R289.1
SIGN2005: C306.2 IC18.8 IC18.14 R281.2
SIGN2006: C307.2 D18.A IC18.12 R283.2
SIGN2008: IC18.13 R290.2
SIGN2009: C303.2 IC18.3
SIGN2010: C304.2 R282.1
SIGN2141: C308.1 D18.C R287.2
SIGN2285: Q36.4 R288.2
SIGN2286: Q35.4 R289.2
SIGN2287: C308.2 IC18.2 L18.1 Q35.1 Q35.2 Q35.3 Q36.5 Q36.6 Q36.7 Q36.8 R291.2
VP_3R3_VOUT_18: C309.1 C312.2 C313.2 C314.2 C461.2 C509.2 C510.2 C537.2 E35.1 IC18.5 L18.2 R292.1 R294.2 R296.2 ; off-sheet VP_3R3_VOUT_18
VP_12R0_VIN_18: C300.2 C301.2 C302.2 C310.2 PJ18.1 Q35.5 Q35.6 Q35.7 Q35.8 R281.1 ; off-sheet VP_12R0_VIN_18
NetIC18_15: IC18.15 R288.1
NetIC18_16: IC18.16 R287.1
NetR285_1: R285.1 R286.2

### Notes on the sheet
- Unless otherwise specified
- Resistors 1/16W (1608)
- Capacitors 50V (1608)
- temperature characteristics X5R
- DC+12V
- INPUT
- (near E35) +3.3V 18.2A 600k(SMALL)
- (near E35) OUTPUT
- (near IC18) 600kHz
- (near E36) GND

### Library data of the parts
C300 = C: as C198 on sheet 8
C301 C302 = C: as C199 on sheet 8
C303 C304 C308 C310 = C: as C201 on sheet 8
C305 = C: SQ_PART_MODEL: CON_47p; FNPARTSNAMEG: CHIP CERAMIC CAPACITOR (1608); USEINPARTSLIST: YES; OriginalSymbolOrigin: (2540,7620); TOLERANCE: J; ASIMVALUE: 47P; CDMASTERCADCELG: C8100E; MFSOLDERINGPROP: .; TEMPCHARACTERI2: CH; MFFORMINGDIVP: KC; OUMECLASSIFICATION: セラミックコンデンサ; SIZECODESMD: 1608; MFMOUNTSYMBOLP: 80; PCODE: P03039A05626; FNCLASSCODEG: P03-03; MAXGCOUNT: 1; RATEDVOLTAGE: 50; COMPONENTNAME: G36030011150; OUMEMAKER: TYD 太陽誘電; MFPACKAGEMETHOP: S; OUMEMAKERKATAMEI: UMK107CH470JZ-T
C306 = C: as C204 on sheet 8
C307 = C: as C205 on sheet 8
C309 = C: as C207 on sheet 8
C311 C312 = C: as C209 on sheet 8
C313 = C: as C211 on sheet 8
C314 = C: as C212 on sheet 8
C461 C462 = C: as C449 on sheet 8
C509 C510 C537 = C: as C497 on sheet 8
D18 = D: as D12 on sheet 8
E35 E36 = EB: as E23 on sheet 8
IC18 = LTC7803UD: as IC12 on sheet 8
L18 = L: USEINPARTSLIST: YES; PARTNAME: 7443310047; OriginalSymbolOrigin: (2540,5080); MAXGCOUNT: 1; COMPONENTNAME: L_L; OUMEMAKER: WURTH
PJ18 = CN2: as PJ12 on sheet 8
Q35 = MFNKR2: as Q23 on sheet 8
Q36 = MFNKR2: USEINPARTSLIST: YES; SAVEAREA0: -9199,-39,32138,22820; TIME: 18:57:44; UPDATEUSER: q91866sr; UPDATETIME: 12:36:02; SAVECOUNT: 10; OriginalSymbolOrigin: (5080,20320); MAXGCOUNT: 1; COMPONENTNAME: MFNKR2_MFNKR2
R281 = R: as R179 on sheet 8
R282 = R: SQ_PART_MODEL: RES_2.2K; FNPARTSNAMEG: CHIP RESISTOR (1608); USEINPARTSLIST: YES; OriginalSymbolOrigin: (5080,5080); MAXGCOUNT: 1; COMPONENTNAME: G36010104339; MFSOLDERINGPROP: .; OUMEMAKER: KOA ＫＯＡ; MFPACKAGEMETHOP: S; MFFORMINGDIVP: KC; MOUNTINGFORMSMD: SMD; OUMECLASSIFICATION: 表面実装用固定抵抗器; RESISTANCETOLER: F; MFMOUNTSYMBOLP: 80; POWERRATING: 63m; OUMEMAKERKATAMEI: RK73H1JTD2201F; NOMINALRESISTAN: 2.2K; NUMBEROFELEMENT: 0; VAL2: 62.5mW; CDMASTERCADCELG: DR802R; PCODE: P01042159428; FNCLASSCODEG: P01-08
R283 = R: SQ_PART_MODEL: RES_100K; FNPARTSNAMEG: CHIP RESISTOR (1608); USEINPARTSLIST: YES; OriginalSymbolOrigin: (5080,5080); TOLERANCE: F; ASIMVALUE: 100K; MFSOLDERINGPROP: .; MFPACKAGEMETHOP: S; MFFORMINGDIVP: KC; MOUNTINGFORMSMD: SMD; MFMOUNTSYMBOLP: 80; NUMBEROFELEMENT: 0; PCODE: P01042045226; MAXGCOUNT: 1; COMPONENTNAME: G36010011057; OUMEMAKER: HDK 北陸電気工業; OUMECLASSIFICATION: 表面実装用固定抵抗器; POWERRATING: 63m; OUMEMAKERKATAMEI: CR1/16 104FV; VAL2: 62.5mW; CDMASTERCADCELG: DR802R; FNCLASSCODEG: P01-08
R284 = R: as R182 on sheet 8
R285 = R: as R183 on sheet 8
R286 = R: as R184 on sheet 8
R287 R290 = R: as R185 on sheet 8
R288 R289 = R: as R186 on sheet 8
R291 = R: SQ_PART_MODEL: RES_1.5K; FNPARTSNAMEG: CHIP RESISTOR (1608); USEINPARTSLIST: YES; OriginalSymbolOrigin: (5080,5080); TOLERANCE: F; ASIMVALUE: 1.5K; MAXGCOUNT: 1; COMPONENTNAME: G36010027232; MFSOLDERINGPROP: .; OUMEMAKER: HDK 北陸電気工業; MFPACKAGEMETHOP: S; MFFORMINGDIVP: KC; MOUNTINGFORMSMD: SMD; OUMECLASSIFICATION: 表面実装用固定抵抗器; MFMOUNTSYMBOLP: 80; POWERRATING: 63m; OUMEMAKERKATAMEI: CR1/16 152FV; NUMBEROFELEMENT: 0; VAL2: 62.5mW; CDMASTERCADCELG: DR802R; PCODE: P01042512223; FNCLASSCODEG: P01-08
R292 = R: SQ_PART_MODEL: RES_68K; FNPARTSNAMEG: CHIP RESISTOR (1608); USEINPARTSLIST: YES; OriginalSymbolOrigin: (5080,5080); TOLERANCE: F; ASIMVALUE: 68K; MAXGCOUNT: 1; COMPONENTNAME: G36010027126; OUMEMAKER: HDK 北陸電気工業; MOUNTINGFORMSMD: SMD; OUMECLASSIFICATION: 表面実装用固定抵抗器; POWERRATING: 63m; OUMEMAKERKATAMEI: CR1/16 683FV; CDMASTERCADCELG: DR802R; MFSOLDERINGPROP: .; MFPACKAGEMETHOP: S; MFFORMINGDIVP: KC; MFMOUNTSYMBOLP: 80; NUMBEROFELEMENT: 0; VAL2: 62.5mW; VAL1: 68K(F); PCODE: P01042456220; FNCLASSCODEG: P01-08
R294 = R: as R192 on sheet 8
R295 = R: as R193 on sheet 8
R296 = R: as R194 on sheet 8
R297 = R: as R195 on sheet 8
U?#12 = WAKU_DEF100: PLOTTIME: HH:MM; SAVEAREA0: 330961,54,387907,31546; TIME: 19:23:07; UPDATEUSER: t5459927; UPDATETIME: 15:33:42; SAVECOUNT: 6; OriginalSymbolOrigin: (10160,284480); DESIGNED: ***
